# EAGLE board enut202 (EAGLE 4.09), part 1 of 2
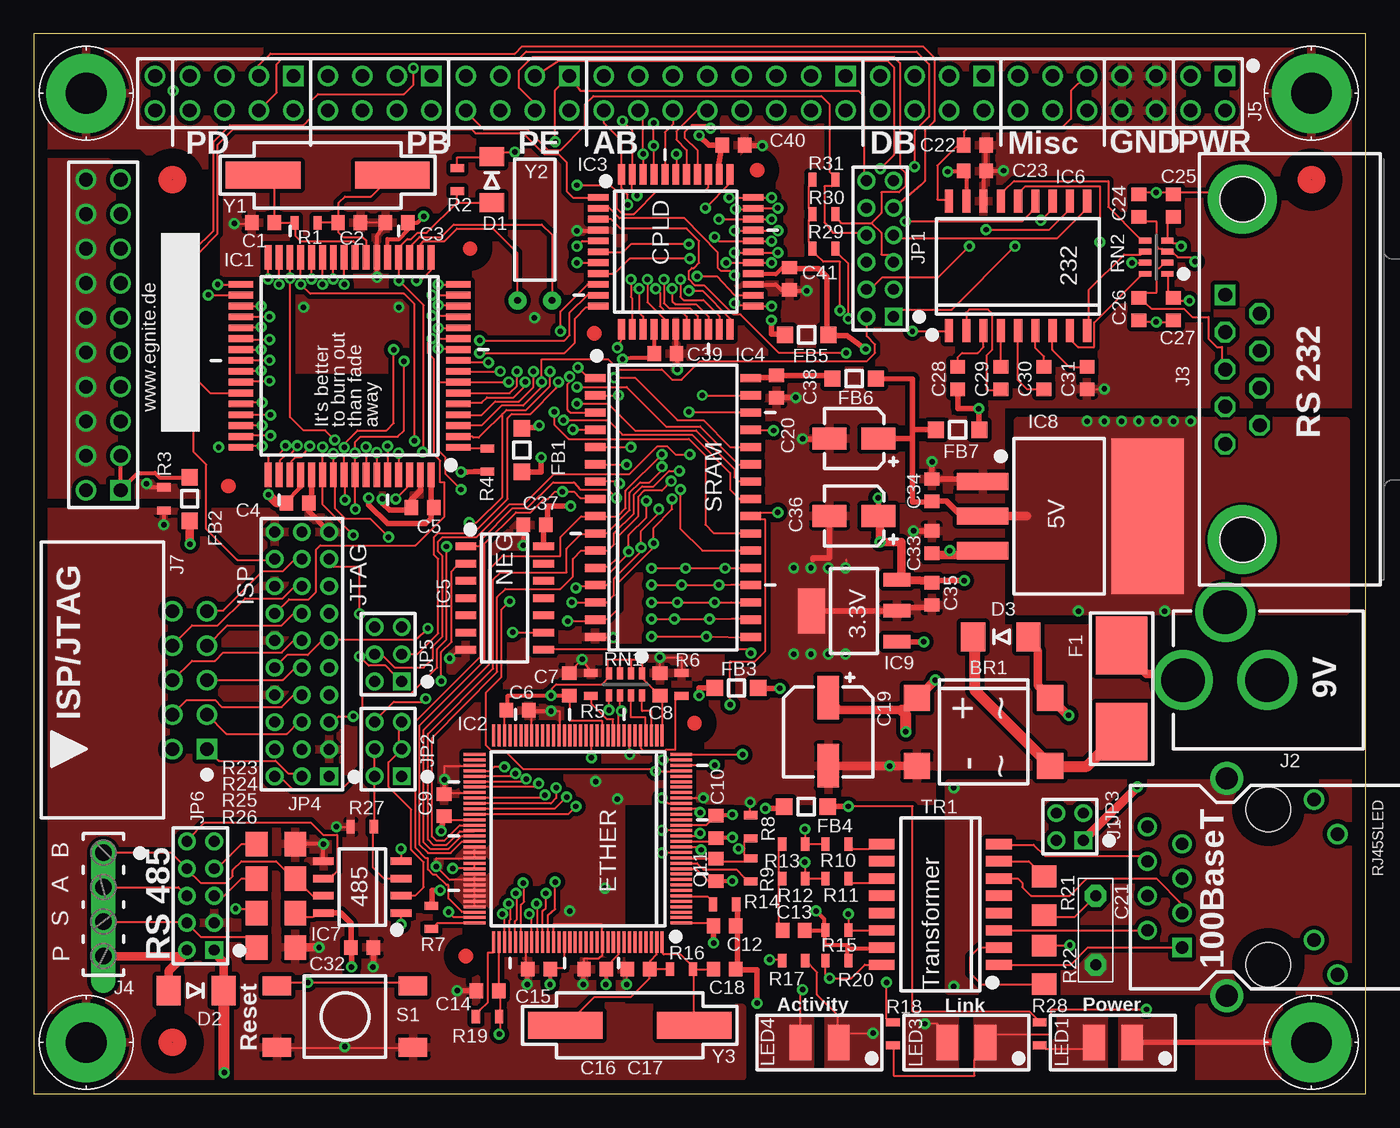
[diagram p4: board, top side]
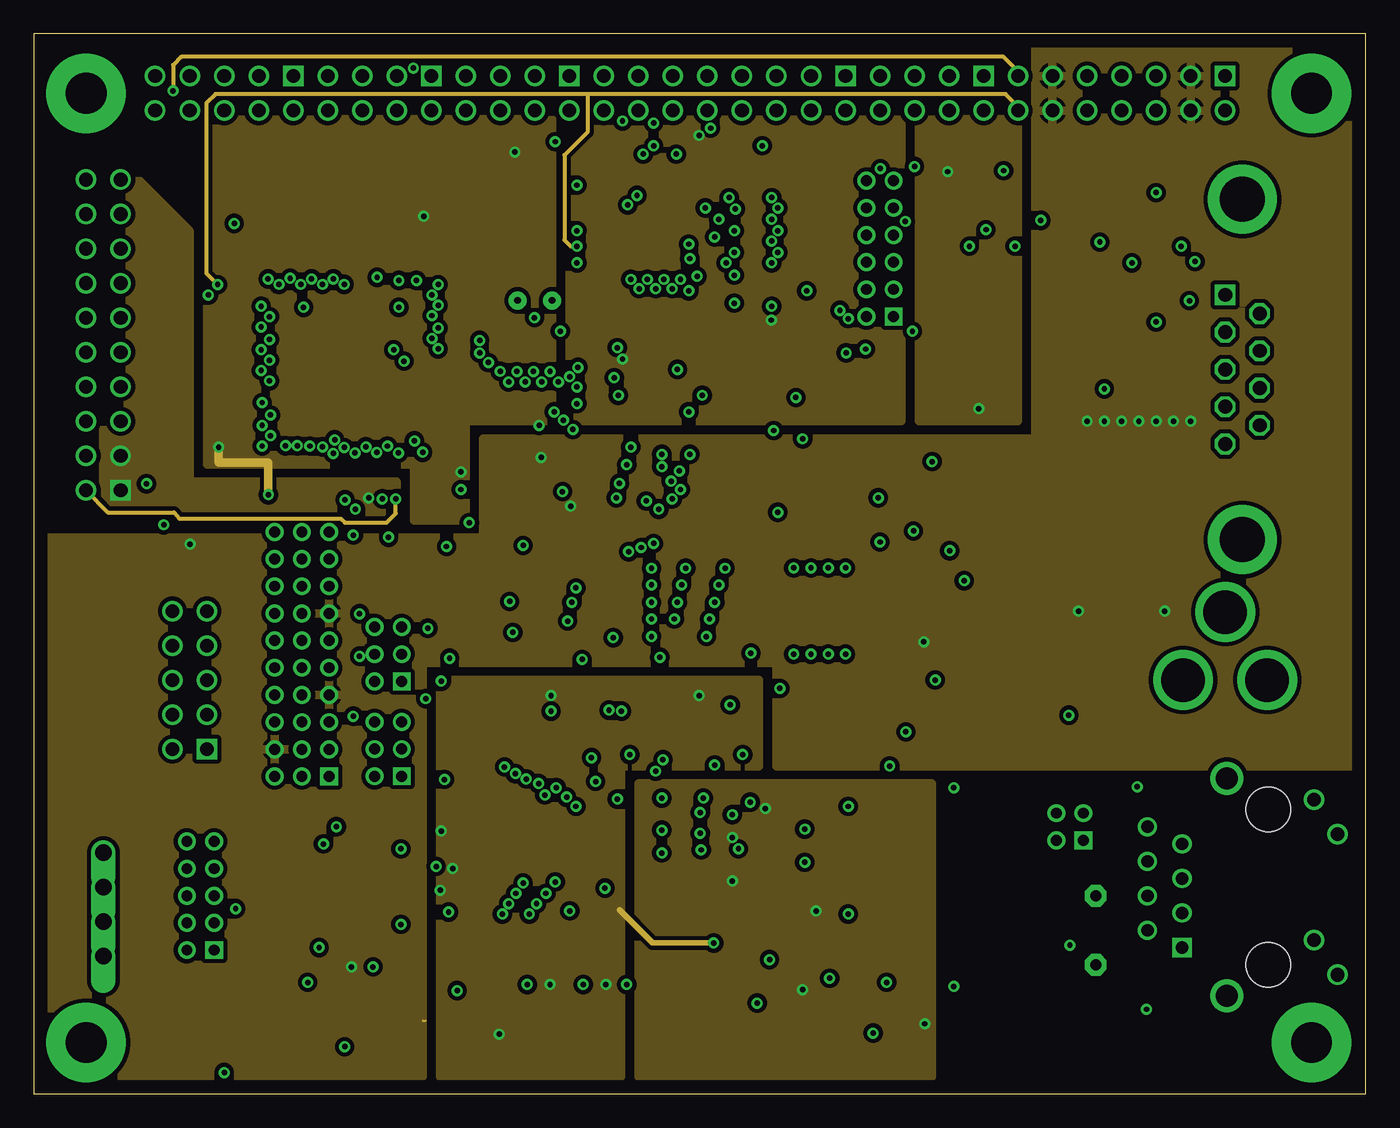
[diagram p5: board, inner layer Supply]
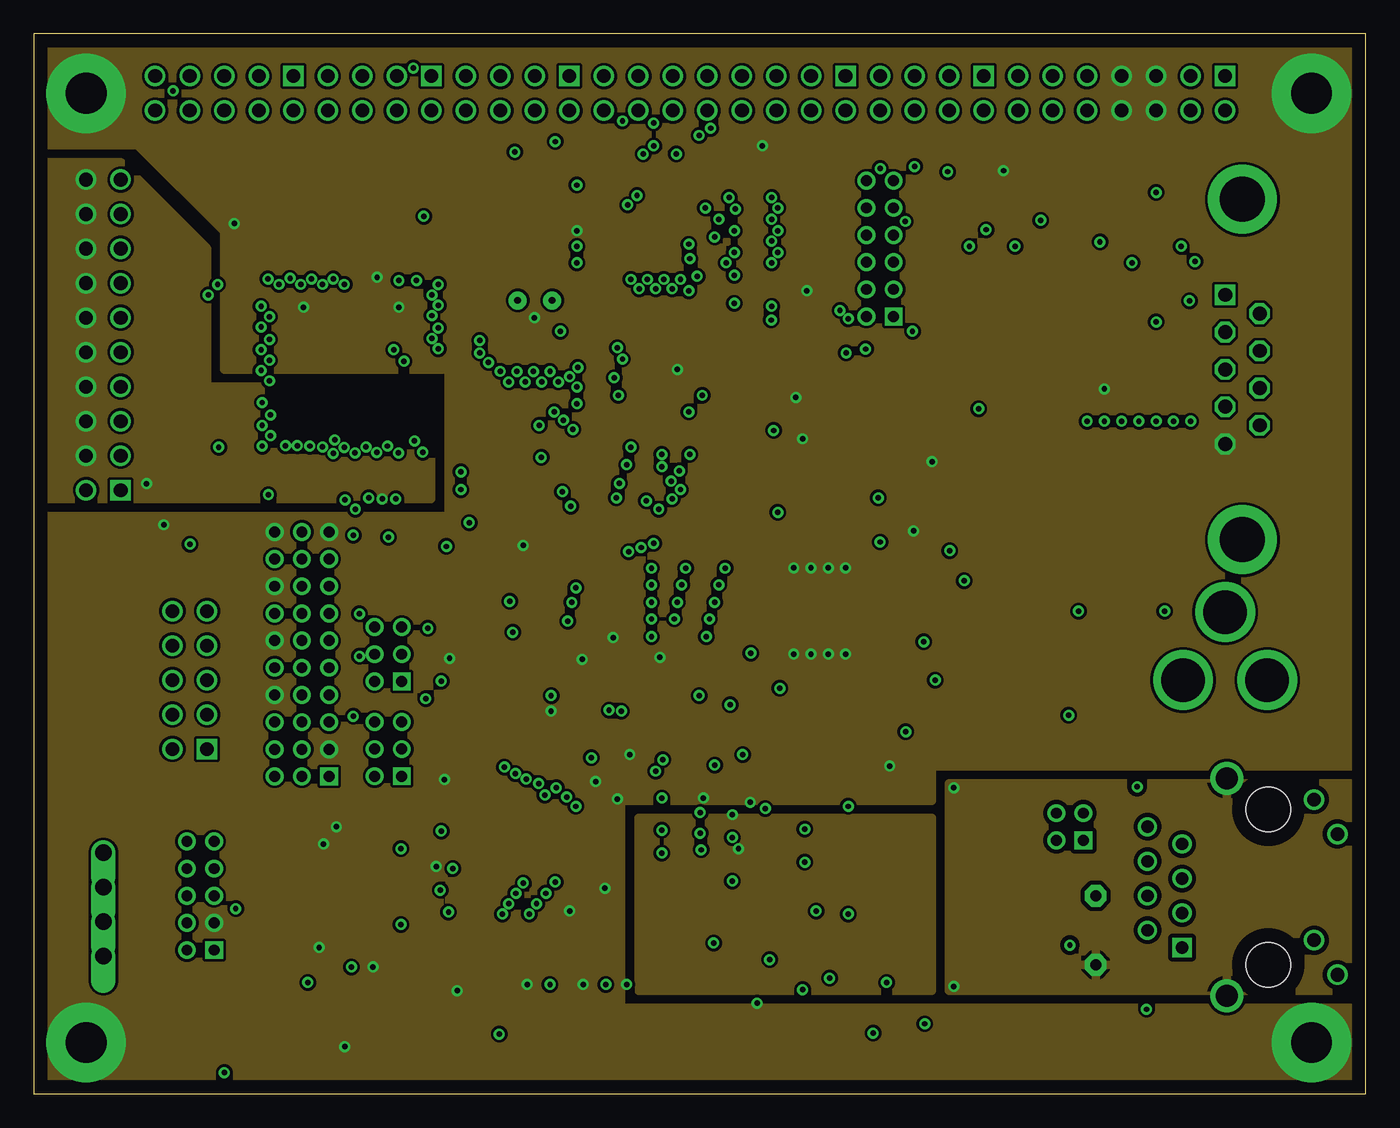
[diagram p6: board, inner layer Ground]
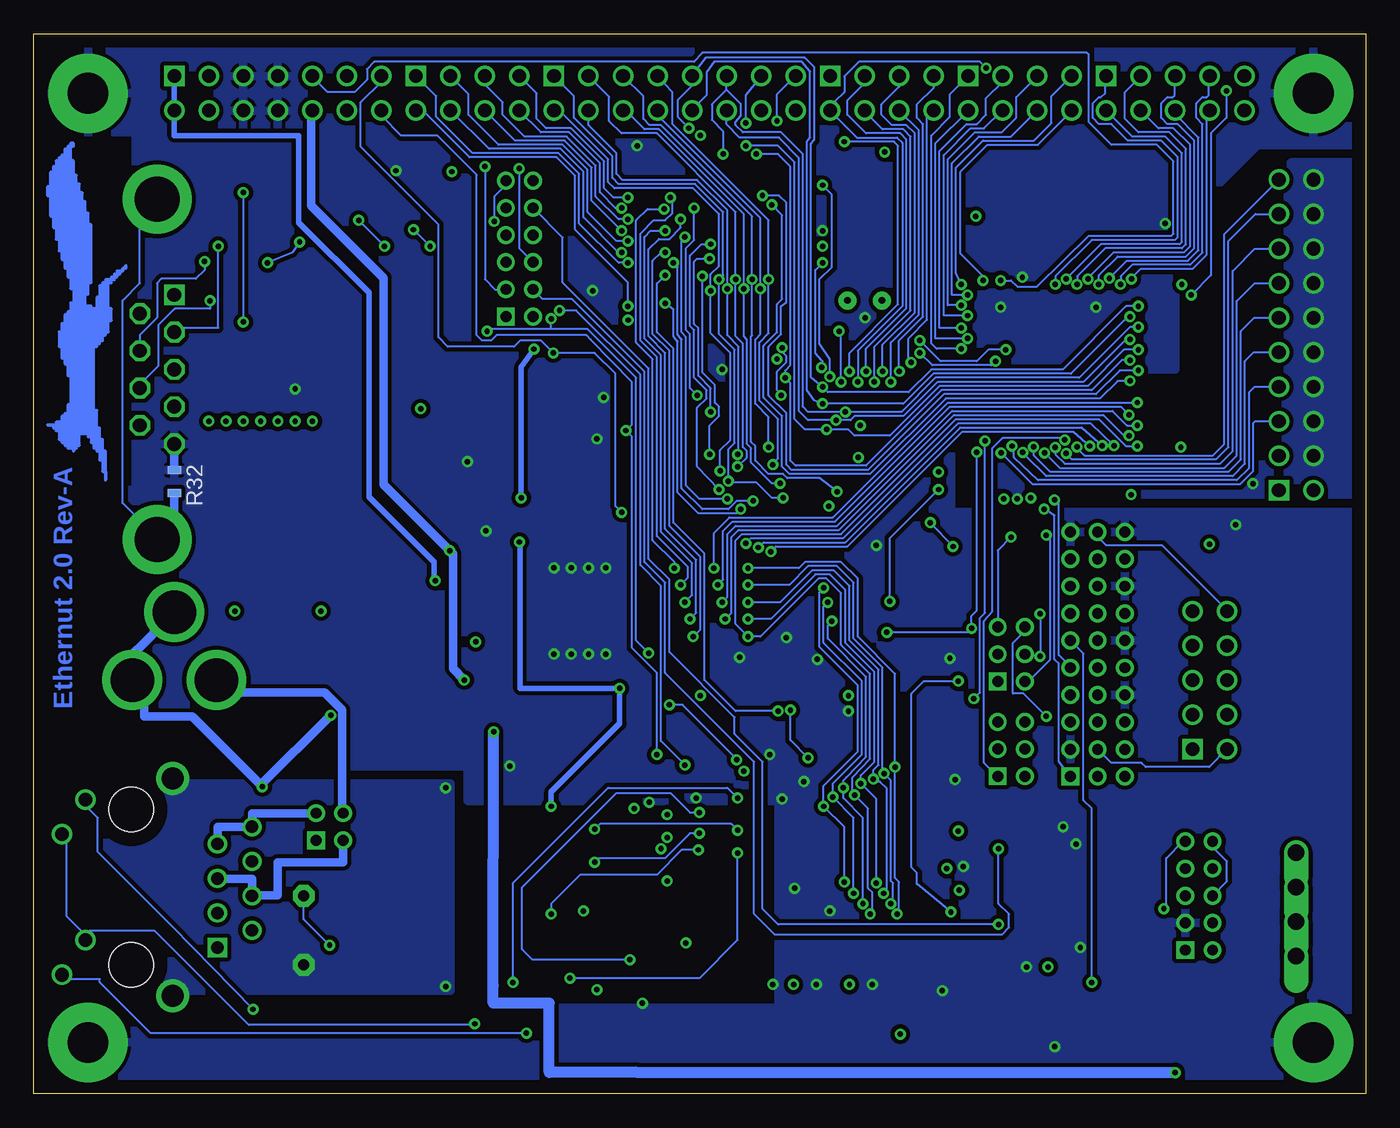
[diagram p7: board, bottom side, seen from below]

Size 97.99 x 78 mm. Coordinates in mm from the lower left corner, seen from the top.
Outline: 0,0 97.99,0 97.99,78 0,78 0,0
Copper layers used: Top, Supply, Ground, Bottom
Net classes: 1 Supply1A: width 0.61 mm

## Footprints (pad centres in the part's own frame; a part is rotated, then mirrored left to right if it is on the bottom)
DFS = smd 1.93 x 1.93: 1 -2.5,-4.9; 2 2.5,-4.9; 3 2.5,4.9; 4 -2.5,4.9
C0603 = smd 0.991 x 1.092: 1 -0.824,0; 2 0.824,0
ALUC6.3 = smd 3.2 x 1.6: + -2.5,0; - 2.5,0
ALUC4.0 = smd 2.5 x 1.6: + -1.8,0; - 1.8,0
C5.0 = drill 0.813 pad 1.6 octagon: 1 -2.54,0; 2 2.54,0
SOD-80C = smd 1.4 x 1.8: A 1.7,0; C -1.7,0
SMB = smd 1.778 x 2.159: A 2.032,0; C -2.032,0
OMNI-BLOK = smd 4.242 x 3.81: 1 -3.175,0; 2 3.175,0
BLM31 = smd 1.2 x 1.2: 1 -1.6,0; 2 1.6,0
MOUNT3 = drill 3 pad 5.842 round: B3,0 0,0
TQFP64 = smd 0.5 x 1.8: 1 -6,-8; 2 -5.2,-8; 3 -4.4,-8; 4 -3.6,-8; 5 -2.8,-8; 6 -2,-8; 7 -1.2,-8; 8 -0.4,-8; 9 0.4,-8; 10 1.2,-8; 11 2,-8; 12 2.8,-8; 13 3.6,-8; 14 4.4,-8; 15 5.2,-8; 16 6,-8; 33 6,8; 34 5.2,8; 35 4.4,8; 36 3.6,8; 37 2.8,8; 38 2,8; 39 1.2,8; 40 0.4,8; 41 -0.4,8; 42 -1.2,8; 43 -2,8; 44 -2.8,8; 45 -3.6,8; 46 -4.4,8; 47 -5.2,8; 48 -6,8 | smd 1.8 x 0.5: 17 8,-6; 18 8,-5.2; 19 8,-4.4; 20 8,-3.6; 21 8,-2.8; 22 8,-2; 23 8,-1.2; 24 8,-0.4; 25 8,0.4; 26 8,1.2; 27 8,2; 28 8,2.8; 29 8,3.6; 30 8,4.4; 31 8,5.2; 32 8,6; 49 -8,6; 50 -8,5.2; 51 -8,4.4; 52 -8,3.6; 53 -8,2.8; 54 -8,2; 55 -8,1.2; 56 -8,0.4; 57 -8,-0.4; 58 -8,-1.2; 59 -8,-2; 60 -8,-2.8; 61 -8,-3.6; 62 -8,-4.4; 63 -8,-5.2; 64 -8,-6
TQFP128 = smd 0.222 x 1.6: 1 -6.2,-7.6; 2 -5.8,-7.6; 3 -5.4,-7.6; 4 -5,-7.6; 5 -4.6,-7.6; 6 -4.2,-7.6; 7 -3.8,-7.6; 8 -3.4,-7.6; 9 -3,-7.6; 10 -2.6,-7.6; 11 -2.2,-7.6; 12 -1.8,-7.6; 13 -1.4,-7.6; 14 -1,-7.6; 15 -0.6,-7.6; 16 -0.2,-7.6; 17 0.2,-7.6; 18 0.6,-7.6; 19 1,-7.6; 20 1.4,-7.6; 21 1.8,-7.6; 22 2.2,-7.6; 23 2.6,-7.6; 24 3,-7.6; 25 3.4,-7.6; 26 3.8,-7.6; 27 4.2,-7.6; 28 4.6,-7.6; 29 5,-7.6; 30 5.4,-7.6; 31 5.8,-7.6; 32 6.2,-7.6; 65 6.2,7.6; 66 5.8,7.6; 67 5.4,7.6; 68 5,7.6; 69 4.6,7.6; 70 4.2,7.6; 71 3.8,7.6; 72 3.4,7.6; 73 3,7.6; 74 2.6,7.6; 75 2.2,7.6; 76 1.8,7.6; 77 1.4,7.6; 78 1,7.6; 79 0.6,7.6; 80 0.2,7.6; 81 -0.2,7.6; 82 -0.6,7.6; 83 -1,7.6; 84 -1.4,7.6; 85 -1.8,7.6; 86 -2.2,7.6; 87 -2.6,7.6; 88 -3,7.6; 89 -3.4,7.6; 90 -3.8,7.6; 91 -4.2,7.6; 92 -4.6,7.6; 93 -5,7.6; 94 -5.4,7.6; 95 -5.8,7.6; 96 -6.2,7.6 | smd 1.6 x 0.222: 33 7.6,-6.2; 34 7.6,-5.8; 35 7.6,-5.4; 36 7.6,-5; 37 7.6,-4.6; 38 7.6,-4.2; 39 7.6,-3.8; 40 7.6,-3.4; 41 7.6,-3; 42 7.6,-2.6; 43 7.6,-2.2; 44 7.6,-1.8; 45 7.6,-1.4; 46 7.6,-1; 47 7.6,-0.6; 48 7.6,-0.2; 49 7.6,0.2; 50 7.6,0.6; 51 7.6,1; 52 7.6,1.4; 53 7.6,1.8; 54 7.6,2.2; 55 7.6,2.6; 56 7.6,3; 57 7.6,3.4; 58 7.6,3.8; 59 7.6,4.2; 60 7.6,4.6; 61 7.6,5; 62 7.6,5.4; 63 7.6,5.8; 64 7.6,6.2; 97 -7.6,6.2; 98 -7.6,5.8; 99 -7.6,5.4; 100 -7.6,5; 101 -7.6,4.6; 102 -7.6,4.2; 103 -7.6,3.8; 104 -7.6,3.4; 105 -7.6,3; 106 -7.6,2.6; 107 -7.6,2.2; 108 -7.6,1.8; 109 -7.6,1.4; 110 -7.6,1; 111 -7.6,0.6; 112 -7.6,0.2; 113 -7.6,-0.2; 114 -7.6,-0.6; 115 -7.6,-1; 116 -7.6,-1.4; 117 -7.6,-1.8; 118 -7.6,-2.2; 119 -7.6,-2.6; 120 -7.6,-3; 121 -7.6,-3.4; 122 -7.6,-3.8; 123 -7.6,-4.2; 124 -7.6,-4.6; 125 -7.6,-5; 126 -7.6,-5.4; 127 -7.6,-5.8; 128 -7.6,-6.2
VQFP44 = smd 0.5 x 1.5: 1 -4,-5.7; 2 -3.2,-5.7; 3 -2.4,-5.7; 4 -1.6,-5.7; 5 -0.8,-5.7; 6 0,-5.7; 7 0.8,-5.7; 8 1.6,-5.7; 9 2.4,-5.7; 10 3.2,-5.7; 11 4,-5.7; 23 4,5.7; 24 3.2,5.7; 25 2.4,5.7; 26 1.6,5.7; 27 0.8,5.7; 28 0,5.7; 29 -0.8,5.7; 30 -1.6,5.7; 31 -2.4,5.7; 32 -3.2,5.7; 33 -4,5.7 | smd 1.5 x 0.5: 12 5.7,-4; 13 5.7,-3.2; 14 5.7,-2.4; 15 5.7,-1.6; 16 5.7,-0.8; 17 5.7,0; 18 5.7,0.8; 19 5.7,1.6; 20 5.7,2.4; 21 5.7,3.2; 22 5.7,4; 34 -5.7,4; 35 -5.7,3.2; 36 -5.7,2.4; 37 -5.7,1.6; 38 -5.7,0.8; 39 -5.7,0; 40 -5.7,-0.8; 41 -5.7,-1.6; 42 -5.7,-2.4; 43 -5.7,-3.2; 44 -5.7,-4
TSOP2-32 = smd 0.6 x 1.5: 1 -9.525,-5.715; 2 -8.255,-5.715; 3 -6.985,-5.715; 4 -5.715,-5.715; 5 -4.445,-5.715; 6 -3.175,-5.715; 7 -1.905,-5.715; 8 -0.635,-5.715; 9 0.635,-5.715; 10 1.905,-5.715; 11 3.175,-5.715; 12 4.445,-5.715; 13 5.715,-5.715; 14 6.985,-5.715; 15 8.255,-5.715; 16 9.525,-5.715; 17 9.525,5.715; 18 8.255,5.715; 19 6.985,5.715; 20 5.715,5.715; 21 4.445,5.715; 22 3.175,5.715; 23 1.905,5.715; 24 0.635,5.715; 25 -0.635,5.715; 26 -1.905,5.715; 27 -3.175,5.715; 28 -4.445,5.715; 29 -5.715,5.715; 30 -6.985,5.715; 31 -8.255,5.715; 32 -9.525,5.715
SO14 = smd 0.559 x 1.524: 1 -3.81,-2.857; 2 -2.54,-2.857; 3 -1.27,-2.857; 4 0,-2.857; 5 1.27,-2.857; 6 2.54,-2.857; 7 3.81,-2.857; 8 3.81,2.857; 9 2.54,2.857; 10 1.27,2.857; 11 0,2.857; 12 -1.27,2.857; 13 -2.54,2.857; 14 -3.81,2.857
SO18W = smd 0.6 x 1.7: 1 -5.08,-4.763; 2 -3.81,-4.763; 3 -2.54,-4.763; 4 -1.27,-4.763; 5 0,-4.763; 6 1.27,-4.763; 7 2.54,-4.763; 8 3.81,-4.763; 9 5.08,-4.763; 10 5.08,4.763; 11 3.81,4.763; 12 2.54,4.763; 13 1.27,4.763; 14 0,4.763; 15 -1.27,4.763; 16 -2.54,4.763; 17 -3.81,4.763; 18 -5.08,4.763
SOIC8 = smd 0.559 x 1.524: 1 -1.905,-2.857; 2 -0.635,-2.857; 3 0.635,-2.857; 4 1.905,-2.857; 5 1.905,2.857; 6 0.635,2.857; 7 -0.635,2.857; 8 -1.905,2.857
DDPAK-ST = smd 1.27 x 3.81: 1 -2.54,-6.413; 2 0,-6.413; 3 2.54,-6.413 | smd 11.43 x 5.334: 4 0,5.715
SOT-223 = smd 1 x 2: 1 -2.261,-3.15; 2 0.025,-3.15; 3 2.311,-3.15 | smd 3.3 x 2: 4 0,3.15
RJ45S = drill 0.9 square: 1 4.445,-6.35 | drill 0.9 round: 2 3.175,-8.89; 3 1.905,-6.35; 4 0.635,-8.89; 5 -0.635,-6.35; 6 -1.905,-8.89; 7 -3.175,-6.35; 8 -4.445,-8.89 | drill 1 round: D1+ 6.452,5.08; D1- 3.912,3.378; D2+ -6.452,3.378; D2- -3.912,5.08 | drill 1.63 round: S1 8.001,-3.048; S2 -8.001,-3.048 | hole 3.3: 5.715,0; -5.715,0
DC2.1 = drill 3.2 pad 4.4 round: 1 -6.91,0; 2 -0.71,0; 3 -3.81,5
SUBD9F = drill 1.016 pad 1.524 square: 1 -5.486,-5.08 | drill 1.016 pad 1.524 octagon: 2 -2.743,-5.08; 3 0,-5.08; 4 2.743,-5.08; 5 5.486,-5.08; 6 -4.115,-2.54; 7 -1.372,-2.54; 8 1.372,-2.54; 9 4.115,-2.54 | drill 3.302 pad 5.08 round: G1 -12.522,-3.81; G2 12.522,-3.81
MINISK = drill 1.2 offset: 1 -3.81,0; 2 -1.27,0; 3 1.27,0; 4 3.81,0
NUTEXP = drill 1 square: 1 39.37,1.27; 15 21.59,1.27; 23 11.43,1.27; 39 -8.89,1.27; 47 -19.05,1.27; 55 -29.21,1.27 | drill 1 round: 2 39.37,-1.27; 3 36.83,1.27; 4 36.83,-1.27; 5 34.29,1.27; 6 34.29,-1.27; 7 31.75,1.27; 8 31.75,-1.27; 9 29.21,1.27; 10 29.21,-1.27; 11 26.67,1.27; 12 26.67,-1.27; 13 24.13,1.27; 14 24.13,-1.27; 16 21.59,-1.27; 17 19.05,1.27; 18 19.05,-1.27; 19 16.51,1.27; 20 16.51,-1.27; 21 13.97,1.27; 22 13.97,-1.27; 24 11.43,-1.27; 25 8.89,1.27; 26 8.89,-1.27; 27 6.35,1.27; 28 6.35,-1.27; 29 3.81,1.27; 30 3.81,-1.27; 31 1.27,1.27; 32 1.27,-1.27; 33 -1.27,1.27; 34 -1.27,-1.27; 35 -3.81,1.27; 36 -3.81,-1.27; 37 -6.35,1.27; 38 -6.35,-1.27; 40 -8.89,-1.27; 41 -11.43,1.27; 42 -11.43,-1.27; 43 -13.97,1.27; 44 -13.97,-1.27; 45 -16.51,1.27; 46 -16.51,-1.27; 48 -19.05,-1.27; 49 -21.59,1.27; 50 -21.59,-1.27; 51 -24.13,1.27; 52 -24.13,-1.27; 53 -26.67,1.27; 54 -26.67,-1.27; 56 -29.21,-1.27; 57 -31.75,1.27; 58 -31.75,-1.27; 59 -34.29,1.27; 60 -34.29,-1.27; 61 -36.83,1.27; 62 -36.83,-1.27; 63 -39.37,1.27; 64 -39.37,-1.27
SLLP2X10 = drill 1 square: 1 -11.43,-1.27 | drill 1 round: 2 -11.43,1.27; 3 -8.89,-1.27; 4 -8.89,1.27; 5 -6.35,-1.27; 6 -6.35,1.27; 7 -3.81,-1.27; 8 -3.81,1.27; 9 -1.27,-1.27; 10 -1.27,1.27; 11 1.27,-1.27; 12 1.27,1.27; 13 3.81,-1.27; 14 3.81,1.27; 15 6.35,-1.27; 16 6.35,1.27; 17 8.89,-1.27; 18 8.89,1.27; 19 11.43,-1.27; 20 11.43,1.27
ML10A = drill 1 pad 1.422 square: 1 -5.08,-6.35 | drill 1 pad 1.422 round: 2 -5.08,-3.81; 3 -2.54,-6.35; 4 -2.54,-3.81; 5 0,-6.35; 6 0,-3.81; 7 2.54,-6.35; 8 2.54,-3.81; 9 5.08,-6.35; 10 5.08,-3.81
SLY2X6 = drill 0.8 square: 1 -5,-1 | drill 0.8 round: 2 -5,1; 3 -3,-1; 4 -3,1; 5 -1,-1; 6 -1,1; 7 1,-1; 8 1,1; 9 3,-1; 10 3,1; 11 5,-1; 12 5,1
SLY2X3 = drill 0.8 square: 1 -2,-1 | drill 0.8 round: 2 -2,1; 3 0,-1; 4 0,1; 5 2,-1; 6 2,1
SLY2X2 = drill 0.8 square: 1 -1,-1 | drill 0.8 round: 2 -1,1; 3 1,-1; 4 1,1
SLY3X10 = drill 0.8 square: 1A -9,-2 | drill 0.8 round: 1B -9,0; 1C -9,2; 2A -7,-2; 2B -7,0; 2C -7,2; 3A -5,-2; 3B -5,0; 3C -5,2; 4A -3,-2; 4B -3,0; 4C -3,2; 5A -1,-2; 5B -1,0; 5C -1,2; 6A 1,-2; 6B 1,0; 6C 1,2; 7A 3,-2; 7B 3,0; 7C 3,2; 8A 5,-2; 8B 5,0; 8C 5,2; 9A 7,-2; 9B 7,0; 9C 7,2; 10A 9,-2; 10B 9,0; 10C 9,2
SLY2X5 = drill 0.8 square: 1 -4,-1 | drill 0.8 round: 2 -4,1; 3 -2,-1; 4 -2,1; 5 0,-1; 6 0,1; 7 2,-1; 8 2,1; 9 4,-1; 10 4,1
P-LCC-2 = smd 1.6 x 2.6: A 1.4,0; C -1.4,0
R0603 = smd 0.6 x 1: 1 -0.85,0; 2 0.85,0
R1206 = smd 1.6 x 1.803: 1 -1.422,0; 2 1.422,0
CAY16 = smd 0.432 x 0.889: 1 -1.219,-0.813; 2 -0.406,-0.813; 3 0.406,-0.813; 4 1.219,-0.813; 5 1.219,0.813; 6 0.406,0.813; 7 -0.406,0.813; 8 -1.219,0.813
LSH = smd 2.1 x 1.4: 1 -5,-2.25; 2 5,-2.25; 3 -5,2.25; 4 5,2.25
SOIC16-12TR = smd 0.762 x 1.905: 1 -4.445,-4.318; 2 -3.175,-4.318; 3 -1.905,-4.318; 4 -0.635,-4.318; 5 0.635,-4.318; 6 1.905,-4.318; 7 3.175,-4.318; 8 4.445,-4.318; 9 4.445,4.318; 10 3.175,4.318; 11 1.905,4.318; 12 0.635,4.318; 13 -0.635,4.318; 14 -1.905,4.318; 15 -3.175,4.318; 16 -4.445,4.318
HC49SM = smd 5.5 x 2: P$1 4.75,0; P$2 -4.75,0
TC38 = drill 0.5 pad 1.321 round: 1 -1.27,-5.08; 2 1.27,-5.08

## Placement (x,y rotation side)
BR1  DF005S  [DFS]  69.88,26.64 270 top
C1  22p  [C0603]  16.86,64.11 180 top
C2  22p  [C0603]  23.21,64.11 0 top
C3  100n  [C0603]  26.7,64.11 180 top
C4  100n  [C0603]  19.4,43.47 0 top
C5  100n  [C0603]  28.61,43.15 180 top
C6  100n  [C0603]  35.59,28.23 0 top
C7  100n  [C0603]  39.4,30.13 90 top
C8  100n  [C0603]  46.07,30.13 90 top
C9  100n  [C0603]  30.19,21.24 90 top
C10  100n  [C0603]  50.2,19.65 90 top
C11  100n  [C0603]  50.2,16.48 90 top
C12  100n  [C0603]  50.83,12.35 0 top
C13  10n  [C0603]  55.91,12.04 180 top
C14  100n  [C0603]  33.37,7.59 180 top
C15  100n  [C0603]  37.18,9.18 180 top
C16  100n  [C0603]  41.3,9.18 180 top
C17  22p  [C0603]  44.48,9.18 180 top
C18  22p  [C0603]  50.83,9.18 0 top
C19  100u 25V  [ALUC6.3]  58.45,26.64 270 top
C20  10u 16V  [ALUC4.0]  60.36,48.23 180 top
C21  1n 2kV  [C5.0]  78.14,12.04 270 top
C22  47n  [C0603]  69.25,69.82 0 top
C23  100n  [C0603]  69.25,67.91 0 top
C24  220p  [C0603]  81.31,65.38 90 top
C25  220p  [C0603]  83.85,65.38 90 top
C26  220p  [C0603]  81.31,57.75 270 top
C27  220p  [C0603]  83.85,57.75 270 top
C28  100n  [C0603]  67.97,52.67 90 top
C29  100n  [C0603]  71.15,52.67 90 top
C30  100n  [C0603]  74.33,52.67 90 top
C31  100n  [C0603]  77.5,52.67 90 top
C32  100n  [C0603]  24.16,10.77 0 top
C33  100n  [C0603]  66.07,40.61 90 top
C34  100n  [C0603]  66.07,44.42 90 top
C35  100n  [C0603]  66.07,36.8 270 top
C36  10u 16V  [ALUC4.0]  60.36,42.52 180 top
C37  100n  [C0603]  36.84,41.88 180 top
C38  100n  [C0603]  54.64,52.04 270 top
C39  100n  [C0603]  46.46,54.47 0 top
C40  100n  [C0603]  51.46,69.82 0 top
C41  100n  [C0603]  55.59,59.98 270 top
D1  LL4148  [SOD-80C]  33.69,67.28 270 top
D2  S1G  [SMB]  11.94,7.59 180 top
D3  SM6T15CA  [SMB]  71.15,33.62 0 top
F1  1A  [OMNI-BLOK]  80.04,29.81 270 top
FB1  BLM31A601  [BLM31]  35.89,47.38 90 top
FB2  BLM31A601  [BLM31]  11.46,43.78 90 top
FB3  BLM31A601  [BLM31]  51.7,29.87 180 top
FB4  BLM31A601  [BLM31]  56.82,21.13 0 top
FB5  BLM31A601  [BLM31]  56.86,55.85 0 top
FB6  BLM31A601  [BLM31]  60.36,52.64 0 top
FB7  BLM31A601  [BLM31]  67.97,48.87 180 top
H1  [MOUNT3]  3.84,73.63 0 top
H2  [MOUNT3]  3.84,3.78 0 top
H3  [MOUNT3]  94.01,73.63 0 top
H4  [MOUNT3]  94.01,3.78 0 top
IC1  ATMEGA128-AC  [TQFP64]  23.23,53.57 90 top
IC2  LAN91C111-NE  [TQFP128]  40.03,18.77 90 top
IC3  XC9536XLVQ44  [VQFP44]  47.23,61.97 270 top
IC4  K6T4008C1C-VB70  [TSOP2-32]  47.02,43.15 270 top
IC5  74HC04D  [SO14]  34.64,36.48 270 top
IC6  MAX3222ECWN  [SO18W]  72.42,60.93 0 top
IC7  SP483ECN  [SOIC8]  24.16,15.21 90 top
IC8  LM1086IS  [DDPAK-ST]  76.23,42.52 270 top
IC9  LM3940IMP  [SOT-223]  60.36,35.53 90 top
J1  RJ45SLED  [RJ45S]  90.84,15.21 270 top
J2  [DC2.1]  91.47,30.45 0 top
J3  [SUBD9F]  92.74,53.31 270 top
J4  [MINISK]  5.11,13.94 270 top
J5  [NUTEXP]  48.29,73.63 0 top
J6  [SLLP2X10]  5.11,55.85 90 top
J7  [ML10A]  6.38,30.45 90 top
JP1  [SLY2X6]  62.26,62.2 90 top
JP2  [SLY2X3]  26.07,25.37 90 top
JP3  [SLY2X2]  76.23,19.65 90 top
JP4  [SLY3X10]  19.71,32.35 90 top
JP5  [SLY2X3]  26.07,32.35 90 top
JP6  JP2X5-1E  [SLY2X5]  12.25,14.58 90 top
LED1  LTST-T670KRKT  [P-LCC-2]  79.41,3.78 180 top
LED3  LTST-T670KGKT  [P-LCC-2]  68.61,3.78 180 top
LED4  LTST-T670KSKT  [P-LCC-2]  57.81,3.78 180 top
R1  1M  [R0603]  20.03,64.11 0 top
R2  10k  [R0603]  31.14,67.28 90 top
R3  0  [R0603]  9.55,43.78 90 top
R4  4k7  [R0603]  33.37,46.64 270 top
R5  10k  [R0603]  40.99,30.13 270 top
R6  10k  [R0603]  47.66,30.13 270 top
R7  10k  [R0603]  29.24,12.99 270 top
R8  0  [R0603]  52.73,19.65 270 top
R9  11k  [R0603]  52.73,16.48 270 top
R10  24.9  [R0603]  59.09,18.38 0 top
R11  24.9  [R0603]  59.09,15.85 0 top
R12  24.9  [R0603]  55.91,15.85 180 top
R13  24.9  [R0603]  55.91,18.38 180 top
R14  10k  [R0603]  50.83,13.94 180 top
R15  49.9  [R0603]  59.09,12.04 180 top
R16  1M  [R0603]  47.66,9.18 180 top
R17  660  [R0603]  55.91,9.81 0 top
R18  660  [R0603]  63.21,4.42 270 top
R19  10k  [R0603]  33.37,5.68 180 top
R20  49.9  [R0603]  59.09,9.81 0 top
R21  75  [R1206]  74.33,14.58 90 top
R22  75  [R1206]  74.33,9.5 270 top
R23  560  [R1206]  17.81,18.38 180 top
R24  120  [R1206]  17.81,15.85 180 top
R25  560  [R1206]  17.81,13.31 0 top
R26  100  [R1206]  17.81,10.77 0 top
R27  10k  [R0603]  24.16,19.65 0 top
R28  660  [R0603]  74.01,4.42 90 top
R29  1k  [R0603]  58.13,62.2 180 top
R30  1k  [R0603]  58.13,64.74 180 top
R31  1k  [R0603]  58.13,67.28 180 top
R32  0  [R0603]  87.66,45.05 270 bottom
RN1  10k  [CAY16]  43.53,30.13 180 top
RN2  22  [CAY16]  82.58,61.56 90 top
S1  LSH  [LSH]  22.89,5.68 180 top
TR1  TG110-S050N2  [SOIC16-12TR]  66.7,13.94 90 top
U$4  [LOGO]  91.23,45.16 90 bottom
U$9  [MARK1]  14.32,44.74 0 top
U$10  [MARK1]  32.1,62.2 0 top
U$11  [MARK1]  31.78,10.13 0 top
U$12  [MARK1]  48.61,27.27 0 top
U$13  [MARK1]  41.23,55.96 0 top
U$14  [MARK1]  53.23,67.97 0 top
U$15  [MARK2]  10.19,67.28 0 top
U$16  [MARK2]  94.01,67.28 0 top
U$17  [MARK2]  10.19,3.78 0 top
Y1  14.7456 MHz  [HC49SM]  21.62,67.6 180 top
Y2  32k768  [TC38]  36.86,63.47 0 top
Y3  25 MHz  [HC49SM]  43.84,5.05 0 top

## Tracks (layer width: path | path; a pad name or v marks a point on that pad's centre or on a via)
A0  (via drill 0.4)
  Top 0.152: 50.47,56.31 IC3.21 50.43,57.24 49.26,58.41 47.81,58.41 47.58,58.64 v47.58,59.94 | v46.89,45.08 46.21,44.39 44.91,44.39 44.45,43.94 44.45,42.49 43.01,41.04 43.01,39.52 42.25,38.76 41.41,38.76 41.36,38.7 IC4.12 | 32.87,40.29 IC5.1 | v42.85,43.86 42.25,44.47 40.19,44.47 39.73,45 38.21,45 36.3,43.1 35.23,43.1 32.87,40.74 32.87,40.29 | 32.41,13.38 IC2.94 31.65,13.38 31.5,13.38 30.51,14.37 30.51,15.36 30.36,15.36 29.6,16.12 29.37,16.12 28.99,16.5 28.99,17.34 28.83,17.34 28.07,18.11 28.07,27.4 32.87,32.2 32.87,40.29
  Bottom 0.152: J5.23 58.25,73.43 58.25,71.83 55.43,69.01 55.43,67.41 54.97,66.95 49.33,66.95 47.27,64.89 47.27,60.24 v47.58,59.94 47.58,55.9 46.44,54.76 46.44,47.9 46.89,47.44 v46.89,45.08 46.82,45 44.84,45 43.69,43.86 v42.85,43.86
A0\  (via drill 0.4)
  Top 0.152: IC2.95 31.65,13 30.89,13 v30.51,13.38 | IC5.2 31.04,38.76 30.74,38.45 30.74,33.27 29.98,32.51 v29.98,30.37
  Bottom 0.152: v29.98,30.37 32.49,30.37 33.41,29.46 33.41,16.66 33.02,16.28 33.02,15.44 v30.51,13.38
A1  (via drill 0.4)
  Top 0.152: IC2.78 | 41.33,39.98 41.33,39.97 | IC4.11 41.33,39.98 | IC3.22 51.23,57.05 49.18,59.1 v48.19,59.1 | v47.5,45.84 46.74,45.84 45.6,44.7 44.76,44.7 44.15,44.09 44.15,42.72 42.7,41.27 42.7,40.43 42.25,39.98 41.33,39.98 | IC4.11 | IC4.11 40.26,39.98 39.65,39.37 39.65,38.07 38.74,37.16 34.7,37.16 34.09,36.55 34.09,31.06 33.94,30.91 29.29,26.18 29.29,18.94 29.6,18.64 30.21,18.64 31.34,19.77 IC2.78 | 41.33,39.98 | 41.33,39.98 | IC2.78 32.43,19.78
  Bottom 0.152: 59.77,72.36 J5.24 59.31,72.36 55.73,68.78 55.73,67.1 55.27,66.64 49.48,66.64 47.58,64.74 47.58,60.93 48.19,60.32 v48.19,59.1 48.19,55.98 46.74,54.53 46.74,48.13 47.5,47.37 v47.5,45.84
A2  (via drill 0.4)
  Top 0.152: 48.87,56.27 IC3.19 48.83,57.24 48.27,57.81 46.74,57.81 46.36,58.19 v46.36,59.94 | v46.21,46.15 46.21,45.92 45.29,45 44.61,45 43.84,44.24 43.84,42.95 42.17,41.27 41.41,41.27 41.38,41.24 IC4.10 41.25,41.19 40.26,41.19 39.2,40.13 39.2,38.38 34.32,38.38 33.79,37.84 33.79,31.29 28.99,26.49 28.99,18.71 29.37,18.33 30.36,18.33 31.35,19.32 32.39,19.32 IC2.79
  Bottom 0.152: J5.25 55.66,73.38 55.66,71.6 54.74,70.68 52.15,70.68 46.36,64.89 v46.36,59.94 46.36,55.75 45.83,55.21 45.83,47.59 45.52,47.29 45.52,46.83 v46.21,46.15
A3  (via drill 0.4)
  Top 0.152: IC2.80 | IC2.80 | IC3.20 49.63,57.2 48.72,58.11 47.2,58.11 46.97,58.34 v46.97,59.25 | v46.21,47.06 43.54,44.39 43.54,43.1 42.93,42.49 41.33,42.49 | 41.33,42.49 IC4.9 | 41.33,42.49 40.26,42.49 38.74,40.97 38.74,39.59 34.47,39.59 33.48,38.6 33.48,31.59 28.68,26.79 28.68,18.49 29.14,18.03 30.51,18.03 31.45,18.97 IC2.80
  Bottom 0.152: v46.21,47.06 46.13,47.14 46.13,54.99 46.97,55.82 v46.97,59.25 46.97,65.05 49.18,67.25 54.66,67.25 55.12,67.71 55.12,69.24 57.18,71.29 J5.26
A4  (via drill 0.4)
  Top 0.152: IC2.81 | IC4.8 41.33,43.77 | IC4.8 | IC2.81 | IC3.16 46.44,56.28 46.36,56.36 | 46.36,56.36 46.44,56.43 | 46.36,56.36 46.36,57.04 45.14,58.26 v45.14,59.94 | 41.39,43.86 IC4.8 | 41.39,43.86 41.41,43.86 | 41.39,43.86 40.19,43.86 39.73,44.32 v38.89,44.32 38.36,44.32 37.83,43.78 37.52,43.78 36.53,42.79 35.46,42.79 33.18,40.51 33.18,31.9 28.38,27.1 28.38,18.33 28.99,17.72 30.66,17.72 31.51,18.57 IC2.81
  Bottom 0.152: J5.27 53.14,73.4 53.14,71.75 52.68,71.29 51.85,71.29 45.14,64.59 v45.14,59.94 45.14,55.82 45.22,55.75 45.22,47.98 44.91,47.67 44.91,46.6 43.92,45.61 42.85,45.61 42.55,45.31 40.19,45.31 v38.89,44.32
A5  (via drill 0.4)
  Top 0.152: IC3.18 | IC3.18 48.04,56.28 | IC3.18 48.03,57.2 47.73,57.5 46.51,57.5 46.05,57.96 46.05,58.95 v45.75,59.25 | IC4.7 41.33,45.08 42.93,45.08 v43.08,44.93 | IC4.7
  Bottom 0.152: v43.08,44.93 43.69,44.93 45.22,46.45 45.22,47.52 45.52,47.82 45.52,55.52 45.75,55.75 v45.75,59.25 45.75,64.74 52,70.99 53.06,70.99 54.44,72.36 J5.28 54.66,72.36
A6  (via drill 0.4)
  Top 0.152: IC3.13 44,56.27 44,58.57 43.92,58.64 v43.92,59.94 | IC4.6 41.3,46.35 41.33,46.38 41.41,46.3 v43.62,46.3
  Bottom 0.152: J5.29 51.01,73.73 51.01,71.37 43.92,64.28 v43.92,59.94 43.92,55.98 44.61,55.29 44.61,51.02 43.23,49.65 43.23,46.76 43.62,46.38 v43.62,46.3
A7  (via drill 0.4)
  Top 0.152: IC3.14 44.83,57.2 44.53,57.5 v44.53,59.25 | 41.33,47.59 | IC4.5 41.33,47.59 | 41.33,47.59 v43.92,47.59
  Bottom 0.152: J5.30 52.15,72.36 52.15,72.05 44.53,64.44 v44.53,59.25 44.53,55.9 44.91,55.52 44.91,50.8 43.92,49.8 v43.92,47.59
A8  (via drill 0.4)
  Top 0.152: IC1.35 15.25,57.96 v16.72,57.96 | v39.96,52.02 43.62,52.02 46.51,49.12 49.03,49.12 51.85,46.3 52.71,46.3 IC4.27 | IC3.37 48.83,69.43 47.88,70.38 47.88,70.76 48.42,71.29 49.41,71.29 v49.79,71.06
  Bottom 0.152: v16.72,57.96 17.63,57.96 22.28,53.31 31.96,53.31 33.63,51.63 39.58,51.63 v39.96,52.02 40.8,52.7 40.8,69.92 40.57,70.23 40.57,75.56 41.25,76.25 48.57,76.25 49.56,74.95 J5.31 49.56,74.19 50.63,73.12 50.63,71.9 v49.79,71.06
A9  (via drill 0.4)
  Top 0.152: IC1.36 15.26,57.2 v17.33,57.2 | v39.96,50.8 42.25,50.8 44.23,48.81 48.72,48.81 51.54,45.99 51.54,45.38 51.85,45.08 52.71,45.08 IC4.26 | J5.32 48.8,72.36 47.27,70.84 47.27,70.23 48.04,69.46 48.03,69.46 IC3.38
  Bottom 0.152: J5.32 49.56,72.44 48.49,73.5 48.49,75.18 47.96,75.94 41.48,75.94 40.87,75.26 40.87,70.38 41.1,70.07 41.1,51.79 40.57,51.02 v39.96,50.8 34.02,50.8 31.8,53 21.67,53 17.48,57.2 v17.33,57.2
A10  (via drill 0.4)
  Top 0.152: IC1.37 15.29,56.43 v16.72,56.43 | IC3.39 47.27,66.95 v47.27,69.16 | v38.28,50.19 38.28,49.27 39.35,48.2 48.19,48.2 49.41,46.98 49.41,41.88 50.02,41.27 52.71,41.27 IC4.23
  Bottom 0.152: 47,74.9 J5.33 47.05,74.88 47.05,73.88 | 47.05,73.88 48.11,72.82 48.11,71.67 47.27,70.84 v47.27,69.16 | 47.05,73.88 45.98,72.82 45.98,71.98 46.36,71.52 46.36,71.29 45.83,70.76 43.01,70.76 41.41,69.16 41.41,50.57 41.03,50.19 v38.28,50.19 34.17,50.19 31.65,52.7 21.06,52.7 17.33,56.43 v16.72,56.43
A11  (via drill 0.4)
  Top 0.152: IC3.40 46.43,70.75 47.05,71.37 47.05,72.33 J5.34 | IC1.38 15.29,55.52 v17.33,55.52 | 52.68,43.78 | 52.68,43.78 IC4.25 | 52.68,43.78 | v38.97,49.58 42.25,49.58 43.31,48.51 48.42,48.51 51.24,45.69 51.24,44.47 51.92,43.78 52.68,43.78
  Bottom 0.152: 47.05,71.67 47.05,71.37 46.05,70.38 43.16,70.38 41.71,68.86 41.71,50.26 41.03,49.58 v38.97,49.58 37.9,49.58 37.6,49.88 34.02,49.88 31.5,52.4 20.76,52.4 17.63,55.52 v17.33,55.52 | 47.05,71.67 47.05,72.36 | 47.05,71.67 J5.34
A12  (via drill 0.4)
  Top 0.152: IC1.39 15.25,54.76 v16.72,54.76 | IC4.4 41.28,48.89 v39.65,48.89 | v45.6,71.45 v45.6,69.77 45.6,67.56 IC3.41
  Bottom 0.152: v45.6,69.77 43.23,69.77 42.02,68.55 42.02,49.65 41.25,48.89 v39.65,48.89 38.05,48.89 37.6,48.43 35.01,48.43 31.35,52.09 20.45,52.09 17.79,54.76 v16.72,54.76 | J5.35 44.45,74.88 45.6,73.5 v45.6,71.45
A13  (via drill 0.4)
  Top 0.152: IC1.40 15.26,54 v17.33,54 | J5.36 44.53,72.36 44.84,72.05 v44.84,69.16 44.84,67.56 IC3.42 | IC4.28 | IC4.28 51.24,47.59 49.26,49.58 47.35,49.58 44.23,52.7 v42.7,52.7
  Bottom 0.152: v44.84,69.16 43.23,69.16 42.32,68.25 42.32,53.62 42.7,53.23 v42.7,52.7 42.32,52.32 42.32,46.6 41.94,46.22 36.76,46.22 31.2,51.79 20.15,51.79 17.94,54 v17.33,54
A14  (via drill 0.4)
  Top 0.152: IC1.41 15.29,53.23 v16.72,53.23 | v43.31,71.6 44.03,70.88 IC3.43 44,67.64 44,66.49 v44.38,66.11
  Bottom 0.152: J5.37 41.99,74.9 43.31,73.58 v43.31,71.6 | v16.72,53.23 18.09,53.23 19.84,51.48 31.04,51.48 36.61,45.92 42.25,45.92 42.63,46.3 42.63,50.11 43.92,51.41 43.92,54.99 43.01,55.9 43.01,57.96 42.63,58.26 42.63,65.58 43.16,66.11 v44.38,66.11
A15  (via drill 0.4)
  Top 0.152: IC1.42 | IC1.42 | IC1.42 15.33,52.47 v17.33,52.47 | J5.38 41.94,71.45 43.23,70.16 IC3.44 43.23,66.64 43.69,66.19 v43.69,65.43
  Bottom 0.152: v17.33,52.47 18.24,52.47 19.54,51.18 30.89,51.18 36.45,45.61 42.4,45.61 42.93,46.15 42.93,49.88 44.3,51.25 44.3,55.06 43.31,56.05 43.31,58.11 42.93,58.49 42.93,64.66 v43.69,65.43
AC1
  Top 0.61: F1.1 81.87,30.91 83.7,30.91 J2.1
  Bottom 0.61: JP3.4 75.32,21.23 75.32,28.24 76.61,29.54 83.7,29.54 J2.1
AC2  (via drill 0.4)
  Top 0.61: D3.A 73.87,32.58 73.87,30.07 BR1.4 75.7,28.24 76.08,27.86 v76.15,27.86 | v81.18,22.6 77.83,19.25 JP3.1
  Bottom 0.61: 81.3,22.72 86.36,27.78 89.87,27.78 89.87,29.54 J2.2 90.78,32.28 89.79,33.27 J2.3 | v81.18,22.6 81.3,22.72 | 81.3,22.72 v76.15,27.86
ACF
  Top 0.813: F1.2 77.5,24.1 74.82,24.1 BR1.3 69.25,29.67 69.25,33.62 D3.C
AGND3  (via drill 0.4)
  Top 0.152: IC2.19 48.42,19.78 49.48,19.78 49.71,20.01 C10.2 | 52.3,18.03 52.3,18.56 R8.2 | 52.3,18.03 52.3,17.57 R9.1 52.3,17.11 50.7,17.11 C11.2 49.71,17.34 48.42,17.34 IC2.13 | 52.3,18.03 v51.85,18.03
  Top 0.305: C10.2 50.26,20.54 v51.39,20.54
  pour Ground (no thermals): 66.07,20.29 44.48,20.29 44.48,7.59 66.07,7.59
AGND5  (via drill 0.4)
  Top 0.305: R3.2 8.55,44.63 v8.29,44.9
  Top 0.406: IC1.63 28.45,45.56 28.45,44.39 27.77,43.71 27.77,43.14 | 27.77,43.1 27.77,43.14 | 27.77,43.14 C5.2 27.78,43.11 27.77,43.1 | v25.63,43.78 25.63,43.48 26.17,42.95 27.69,42.95 27.77,43.1
  pour Ground (no thermals): 0.67,68.55 6.38,68.55 12.73,62.2 12.73,52.04 29.24,52.04 29.24,43.78 0.67,43.78
  pour Bottom (isolate 0.305, no thermals): 0.67,68.55 5.43,68.55 12.73,61.25 12.73,52.04 29.24,52.04 29.24,44.1 0.67,44.1
  pour Top (isolate 0.305, no thermals): 0.67,68.55 5.43,68.55 12.73,61.25 12.73,52.04 29.24,52.04 29.24,44.1 0.67,44.1
ALE
  Top 0.152: 15.17,51.63 IC1.43 15.22,51.56 12.98,51.56 12.07,52.47 12.07,61.84 13.52,63.29 13.52,69.84 14.66,70.99 32.19,70.99 32.49,70.68 36,70.68 37.52,69.16 38.59,69.16 39.2,68.55 39.2,66.42 39.65,65.96 41.48,65.96 41.49,65.97 IC3.1
AREF  (via drill 0.4)
  Top 0.152: IC1.62 27.63,44.8 v26.62,43.78
  Supply 0.305: v26.62,43.78 26.62,42.72 25.94,42.03 22.89,42.03 22.59,42.34 10.7,42.34 10.32,42.79 5.44,42.79 3.84,44.39 J6.2
AVCC3  (via drill 0.4)
  Top 0.152: IC2.16 50.17,18.56 50.17,18.83 | 50.17,18.83 50.17,18.87 | 50.17,18.83 C10.1 | 50.25,15.66 50.25,15.59 | 50.25,15.66 C11.1 49.64,15.67 48.73,16.57 IC2.11 | 50.25,15.66 50.25,15.67 | 58.25,12.04 R15.2 58.21,12.01 | 59.92,9.88 59.94,9.86 R20.2 | 62.34,10.71 TR1.15 | 56.72,12.01 C13.1 | LED4.A 56.42,7.51 v56.57,7.67 | LED3.A 66.48,5.15 v65.56,5.15
  Top 0.305: 59.85,10.94 59.92,10.94 | 59.85,10.71 59.85,10.94 | 59.85,10.94 58.21,10.94 58.21,12.01 58.17,12.01 | 59.85,10.71 62.34,10.71 | 59.85,10.71 59.85,9.88 59.92,9.88 | v57.56,13.46 58.17,12.85 58.17,12.01 | 58.17,12.01 56.72,12.01 | 50.25,15.67 v51.39,15.67 | 50.17,18.87 v51.39,18.87
  Top 0.406: FB4.1 55.09,21 v53.83,21
  Bottom 0.152: J1.D2- 95.59,18.41 95.59,13.08 94.52,12.01 J1.D1- 93.91,12.01 89.11,12.01 82.17,5.08 65.64,5.08 v65.56,5.15
  pour Supply (isolate 0.305): 44.48,22.83 66.07,22.83 66.07,1.24 44.48,1.24
  pour Top (isolate 0.305, no thermals): 64.04,5.76 68,5.76 68,1.8 64.04,1.8
  pour Top (isolate 0.305, no thermals): 53.37,5.76 57.33,5.76 57.33,1.8 53.37,1.8
AVCC5  (via drill 0.4)
  Top 0.152: FB2.2
  Top 0.305: J6.3 J6.1 7.65,45.69 8.92,45.69 9.24,45.37 FB2.2 | 29.25,45.57 IC1.64
  Top 0.406: 29.21,43.17 29.4,43.17 C5.1 | 29.25,45.57 29.21,45.54 29.21,43.17 | 29.21,43.17 29.21,42.34 28.83,41.96 26.01,41.96 24.64,43.33 v24.64,43.86
  pour Supply (isolate 0.305, rank 2, no thermals): 5.11,68.55 6.38,68.55 11.46,63.47 11.46,45.05 26.7,45.05 26.7,42.2 5.11,42.2
BE2\
  Top 0.152: R7.2 29.27,12.14 29.7,12.57 IC2.96
CYCLE\
  Top 0.152: IC2.35 45.45,26.38 45.45,28.16 44.75,28.16 RN1.8
D0  (via drill 0.4)
  Top 0.152: IC2.76 | IC2.76 | 52.99,61.23 | 52.99,61.23 IC3.27 51.62,61.17 v50.93,61.16 | 52.99,61.23 53.06,61.23 53.14,61.16 v54.28,61.16 | v20.3,47.67 19.61,46.83 19.23,46.83 18.93,46.53 18.93,45.61 18.87,45.61 IC1.51 | v39.88,37.23 40.04,37.38 41.12,37.38 41.13,37.37 41.23,37.47 41.27,37.44 IC4.13 41.3,37.38 41.33,37.41 41.33,37.46 42.17,37.46 42.4,37.69 42.4,38.38 43.77,39.75 v43.77,39.9 43.77,41.12 45.06,42.41 v45.06,43.63 | IC2.107 37.83,13.15 38.36,13.61 v38.36,15.59 | IC2.76 39.3,20.57 v39.88,21.15
  Bottom 0.152: J5.15 69.86,74.9 68.38,73.43 68.38,71.9 65.71,69.24 59.39,69.24 57.87,67.71 57.87,64.05 54.97,61.16 v54.28,61.16 | v45.06,43.63 46.28,43.63 46.89,43.02 48.8,43.02 50.32,44.55 50.32,55.52 50.63,55.9 50.63,60.85 v50.93,61.16 | v39.88,37.23 40.19,36.93 40.19,32.89 37.37,30.07 37.37,25.19 39.88,22.68 v39.88,21.15 38.36,19.63 v38.36,15.59 | v20.3,47.67 21.52,48.74 29.67,48.74 38.13,40.28 43.39,40.28 v43.77,39.9
D1  (via drill 0.4)
  Top 0.152: IC2.75 | IC2.75 | 41.23,36.16 41.23,36.17 | 41.23,36.16 IC4.14 | 52.99,58.03 52.99,58.02 | 52.99,58.02 IC3.23 | v19.38,47.69 18.82,46.98 18.47,46.98 18.09,46.6 18.09,45.61 18.07,45.61 IC1.50 | IC4.14 | 41.23,36.16 | v39.58,36.16 41.23,36.16 | IC2.106 37.44,11.18 37.44,13.46 37.67,13.69 v37.67,14.75 | v45.98,43.02 45.98,42.72 44.68,41.42 v44.68,40.2 44.68,39.9 42.7,37.92 42.7,36.7 42.17,36.16 IC4.14 | 52.99,58.02 52.98,58.03 52.99,58.03 | 53.06,58.02 53.06,58.03 | 52.99,58.02 53.06,58.02 | v54.28,57.96 53.06,57.96 53.06,58.02 | v51.54,58.19 51.69,58.03 52.99,58.03 | IC2.75 38.33,20.97 v39.2,21.84
  Bottom 0.152: J5.16 69.37,72.36 65.94,68.93 59.54,68.93 58.17,67.56 58.17,63.6 54.28,59.71 v54.28,57.96 | v39.58,36.16 39.88,35.86 39.88,33.19 37.06,30.37 37.06,24.96 39.2,22.83 v39.2,21.84 37.67,20.31 v37.67,14.75 | v19.38,47.69 20.88,49.04 29.82,49.04 38.28,40.59 44.3,40.59 v44.68,40.2 | v51.54,58.19 50.93,57.73 50.93,55.75 50.63,55.37 50.63,44.24 49.1,42.72 46.28,42.72 v45.98,43.02
D2  (via drill 0.4)
  Top 0.152: IC2.74 | IC2.74 | 52.91,62.76 IC3.29 52.91,62.76 | 52.91,62.76 v54.28,62.76 | v18.51,47.69 18.51,47.55 17.94,46.98 17.25,46.98 17.25,45.57 IC1.49 | v39.27,34.79 41.2,34.79 IC4.15 41.3,34.95 41.33,34.97 41.33,34.95 42.25,34.95 43.01,35.71 43.01,37.61 45.6,40.2 v45.6,40.51 45.6,41.65 46.97,43.02 v46.97,43.78 | IC2.105 37.06,11.2 37.06,13.92 v36.99,13.99 | 52.91,62.76 50.4,62.76 v50.09,63.06 | IC2.74 38.04,21.37 38.44,21.76 v38.44,22.52
  Bottom 0.152: v39.27,34.79 39.58,34.49 39.58,33.5 36.76,30.68 36.76,24.81 38.21,23.29 38.44,23.06 v38.44,22.52 38.44,21.76 36.99,20.31 | v18.51,47.69 20.24,49.35 29.98,49.35 38.44,40.89 45.22,40.89 v45.6,40.51 | v50.09,63.06 50.32,62.84 50.32,56.05 50.02,55.67 50.02,44.78 49.03,43.78 v46.97,43.78 | v36.99,13.99 36.99,20.31 | 36.99,20.31 36.99,20.33 | J5.17 66.02,73.58 66.02,72.05 63.81,69.84 59.09,69.84 57.26,68.02 57.26,64.89 55.12,62.76 v54.28,62.76
D3  (via drill 0.4)
  Top 0.152: IC2.73 | IC2.73 | 52.73,33.57 IC4.17 52.68,33.57 v49.48,33.65 v45.45,33.65 | IC3.28 52.96,62 52.91,62 52.99,61.92 | 52.99,61.92 v54.74,61.92 | v51.54,61.92 52.99,61.92 | IC1.48 15.27,47.61 15.27,47.67 v16.79,47.67 | IC2.104 36.61,11.2 36.61,13.08 v36.45,13.23 | IC2.73 37.38,21.77 v37.6,21.99
  Bottom 0.152: J5.18 67.31,72.36 64.5,69.54 59.24,69.54 57.56,67.86 57.56,64.51 54.97,61.92 v54.74,61.92 | v16.79,47.67 17.63,47.67 19.61,49.65 30.13,49.65 38.59,41.19 45.9,41.19 46.36,40.74 46.36,34.56 v45.45,33.65 44.53,33.65 40.26,37.92 39.65,37.92 38.59,36.85 38.59,33.04 36.45,30.91 36.45,24.66 37.75,23.29 37.75,22.14 v37.6,21.99 36.61,21 36.61,15.13 36.3,14.83 36.3,13.38 v36.45,13.23 | v51.54,61.92 51.85,61.92 52.46,61.31 52.46,55.9 51.24,54.68 51.24,41.8 48.95,39.52 48.95,34.18 v49.48,33.65
D4  (via drill 0.4)
  Top 0.152: IC2.71 | IC2.71 | IC4.18 52.73,34.97 51.34,34.97 v49.71,34.95 v47.12,34.95 v45.45,34.95 | 52.92,64.36 IC3.31 | 52.92,64.36 52.91,64.36 | 52.99,64.28 52.92,64.35 52.92,64.36 | v54.28,64.36 53.06,64.36 52.99,64.28 | 52.99,64.28 52.99,64.36 v50.4,64.36 | IC1.47 15.37,48.51 15.45,48.43 v17.4,48.43 | IC2.102 35.84,11.18 35.84,13.92 36.07,14.14 36.07,15.44 v36,15.52 | IC2.71 36.88,22.57 v37.14,22.83
  Bottom 0.152: v54.28,64.36 54.97,64.36 56.65,66.03 56.65,68.32 58.78,70.45 61.9,70.45 63.51,72.05 63.51,72.97 64.8,74.27 J5.19 | v17.4,48.43 17.79,48.43 19.31,49.96 30.28,49.96 38.74,41.5 46.13,41.5 46.66,40.97 46.66,35.4 v47.12,34.95 | v45.45,34.95 43.77,34.95 40.49,38.22 39.43,38.22 38.28,37.08 38.28,33.19 36.15,31.06 36.15,24.43 37.14,23.44 v37.14,22.83 36,21.69 v36,15.52 | v49.71,34.95 49.26,35.4 49.26,39.29 51.54,41.57 51.54,54.53 52.76,55.75 52.76,62.15 52,62.91 51.24,62.91 50.4,63.75 v50.4,64.36
D5  (via drill 0.4)
  Top 0.152: IC2.70 | IC2.70 | IC2.70 36.03,22.97 v36.23,23.17 | IC4.19 51.32,36.17 | 52.91,63.52 52.91,63.55 IC3.30 52.93,63.54 52.91,63.52 | 52.91,63.52 v54.74,63.52 | v51.54,63.52 52.91,63.52 | v50.09,36.16 51.32,36.17 | v50.09,36.16 51.31,36.17 51.32,36.17 | v50.09,36.16 v47.35,36.16 v45.45,36.16 | IC1.46 15.26,49.2 v16.79,49.2 | v35.46,14.75 35.54,14.68 35.54,12.85 35.39,12.7 35.39,11.21 IC2.101
  Bottom 0.152: v54.74,63.52 56.95,65.73 56.95,68.17 58.93,70.15 62.59,70.15 J5.20 | v16.79,49.2 17.56,49.2 18.62,50.26 30.43,50.26 38.89,41.8 46.36,41.8 46.97,41.19 46.97,36.55 v47.35,36.16 | v35.46,14.75 35.23,14.98 35.23,22.47 35.73,22.97 36.03,22.97 v36.23,23.17 36.23,23.82 35.84,24.2 35.84,31.21 37.98,33.35 37.98,37.38 39.12,38.53 40.72,38.53 43.08,36.16 v45.45,36.16 | v51.54,63.52 52.61,63.52 53.06,63.06 53.06,55.6 51.85,54.38 51.85,41.35 49.56,39.06 49.56,36.7 v50.09,36.16
D6  (via drill 0.4)
  Top 0.152: IC2.69 | IC2.69 | v35.43,23.57 35.23,23.37 IC2.69 | 15.33,49.97 | 15.33,49.97 IC1.45 | IC4.20 52.73,37.47 51.32,37.47 v50.4,37.46 v47.66,37.46 v45.45,37.46 | IC3.33 52.91,65.96 | IC3.33 | IC3.33 v54.28,65.96 | v51.16,65.96 IC3.33 | 15.33,49.97 15.34,49.96 v17.4,49.96 | IC2.100 35.01,11.2 | v34.93,13.99 35.08,13.84 35.08,12.85 35.01,12.77 35.01,11.2 | 35.01,11.2 35.01,11.17
  Bottom 0.152: v51.16,65.96 51.01,65.73 51.01,64.82 51.54,64.28 52.38,64.28 53.37,63.29 53.37,55.44 52.15,54.22 52.15,41.04 49.87,38.76 49.87,37.99 v50.4,37.46 | v54.28,65.96 55.35,65.96 56.04,66.64 56.04,68.63 58.48,71.06 60.3,71.06 60.99,71.75 60.99,73.63 J5.21 | v17.4,49.96 18.01,50.57 30.59,50.57 39.04,42.11 46.59,42.11 47.27,41.42 47.27,37.84 v47.66,37.46 | v34.93,13.99 34.78,14.14 34.78,15.52 34.93,15.67 34.93,23.07 v35.43,23.57 35.45,23.59 35.46,23.59 35.54,23.67 35.54,31.36 37.67,33.5 37.67,37.61 38.89,38.83 41.03,38.83 42.4,37.46 v45.45,37.46
D7  (via drill 0.4)
  Top 0.152: IC2.68 | IC2.68 | IC1.44 | IC1.44 | 52.7,38.67 IC4.21 52.71,38.68 v50.86,38.68 v47.96,38.68 v45.45,38.68 | v54.74,65.2 52.96,65.2 IC3.32 52.88,65.12 v51.62,65.12 | 15.27,50.8 15.25,50.77 IC1.44 | 15.27,50.8 15.29,50.78 | 15.27,50.8 15.35,50.87 v16.79,50.87 | v34.47,13.23 34.62,13.23 IC2.99 | v34.62,24.05 33.86,24.05 33.56,23.74 32.49,23.74 32.47,23.77 IC2.68
  Bottom 0.152: J5.22 62.29,72.36 60.69,70.76 58.63,70.76 56.34,68.47 56.34,66.34 55.2,65.2 v54.74,65.2 | v16.79,50.87 30.74,50.87 39.2,42.41 46.82,42.41 47.96,41.27 v47.96,38.68 | v34.47,13.23 34.32,13.38 34.32,15.59 34.62,15.9 v34.62,24.05 34.62,30.91 37.37,33.65 37.37,37.92 38.59,39.14 41.25,39.14 41.71,38.68 v45.45,38.68 | v51.62,65.12 52.84,65.12 53.68,64.28 53.68,55.29 52.46,54.07 52.46,40.74 50.86,39.14 v50.86,38.68
DC  (via drill 0.4)
  Top 0.61: 66.23,39.98 66.07,39.82 C33.1 66.55,39.67 67.39,39.67 | BR1.1 64.04,28.24 59.24,28.24 C19.+ | 67.39,39.67 67.92,39.67 IC8.3 | v67.39,39.98 67.39,39.67 | v66.32,30.45 65.94,30.07 BR1.1 | JP6.1 13.25,10.5 13.21,10.45 13.97,9.69 D2.C 14,7.59 | BR1.1 64.04,28.19 64.17,27.91
  Top 0.813: v14,1.56 14,7.59 | v64.17,26.64 64.17,27.91 63.85,28.23
  Bottom 0.61: J5.10 77.6,71.67 77.6,65.35 72.27,60.02 72.27,44.85 v67.39,39.98 67.16,39.75 67.16,31.29 v66.32,30.45
  Bottom 0.813: v14,1.56 53.6,1.56 53.6,1.57 60.08,1.57 60.08,6.68 64.19,6.68 64.19,7.97 v64.17,26.64
DCX
  Top 0.61: J4.4 | J4.4 10.81,10.13 JP6.2 11.25,10.5 11.3,10.45 9.9,9.05 D2.A
DE485
  Top 0.152: IC7.3 25.75,15.85 24.95,16.64 24.95,19.02 R27.2 24.95,19.65 25.07,19.77 JP2.2 | JP2.2 JP2.4 | JP2.2 25.07,23.35
DIHO  (via drill 0.4)
  Top 0.152: IC7.4 26.93,17.11 27.01,17.19 v27.01,18.03 | v70.06,63.6 74.71,63.6 76,64.89 IC6.11 | v68.84,62.38 66.55,60.09 62.44,60.09 61.83,59.48 JP1.4
  Bottom 0.152: 29.67,11.71 26.78,11.71 26.24,12.24 26.24,13.23 27.01,13.99 v27.01,18.03 | JP1.4 60.55,58.49 58.4,58.49 53.06,53.16 53.06,39.14 51.54,37.61 51.54,30.98 44.99,24.43 44.99,13.23 43.46,11.71 29.67,11.71 | v68.84,62.38 v70.06,63.6 | 29.67,11.71 29.75,11.71
ENEEP
  Top 0.152: R14.2 49.71,14.37 49.56,14.52 48.42,14.52 IC2.6
GND  (via drill 0.4)
  Top 0.152: 66.07,45.21 C34.2 65.94,45.24 | 69.66,45.21 IC8.1 69.88,45.12 | 63.53,35.53 IC9.2 63.48,35.53 | IC9.4 57.18,35.53 | C36.- 58.61,42.52 | v30.59,32.05 30.66,32.05 31.04,32.43 IC5.7 | v42.63,33.57 42.02,33.57 IC4.16 | IC1.53 | IC1.53 | IC3.17 | IC3.17 | v22.26,19.65 R27.1 | C31.1 77.53,51.88 v78.77,51.88 | 59.77,39.29 59.79,39 | C3.2 25.84,64.11 25.79,64.05 25.73,64.11 C2.2 | C1.2 16.03,64.13 15.96,64.05 v14.74,64.05 | 32.41,13.79 IC2.93 32.43,13.84 | 32.41,17.75 32.41,17.34 31.65,17.34 | 32.41,17.75 IC2.83 | IC2.82 32.41,18.15 32.41,17.75 | 32.43,16.2 IC2.87 32.43,15.82 | IC2.88 32.43,15.82 | 32.43,15.82 32.41,15.82 | IC2.89 IC2.88 | IC2.89 32.41,15.36 | IC2.90 32.43,14.6 | IC2.90 IC2.89 | IC2.90 32.41,14.98 | 32.43,14.6 IC2.91 32.43,14.22 | 32.43,14.6 32.41,14.6 | 32.43,14.22 IC2.92 32.43,13.84 | 32.43,14.22 32.41,14.22 | 32.43,13.84 32.41,13.84 | IC2.72 32.41,22.14 30.27,22.14 C9.2 | IC2.103 36.23,9.31 C15.2 | IC2.57 36.61,26.39 36.61,28.04 C6.2 | C16.2 40.49,9.18 40.49,9.95 41.56,9.95 41.83,10.23 IC2.117 41.79,11.17 41.79,12.47 38.21,12.47 38.21,11.17 IC2.108 | C17.2 43.62,9.18 v43.62,8.05 | IC2.24 47.66,21.77 47.66,21.76 v49.26,21.76 | R8.1 52.71,20.82 v52.71,21.46 | IC2.67 32.39,24.12 30.21,24.12 v30.21,23.13 | IC2.39 43.84,26.37 v43.84,24.96 | IC2.52 38.66,26.37 38.66,28.16 v38.05,28.16 | C7.2 39.4,31.03 v40.34,31.97 40.95,31.06 R5.1 | R6.1 47.66,32.13 v46.05,32.13 46.07,32.13 C8.2 | 51.69,9.18 51.69,9.19 | 51.69,9.18 C18.2 | 51.69,9.11 51.69,9.18 | 31.65,17.34 29.6,17.34 v29.6,16.73 30.59,15.74 32.41,15.74 32.41,15.75 IC2.88 | 31.65,17.34 IC2.84 | 27.85,3.4 S1.3 | S1.4 17.86,3.41 17.86,3.4 22.8,3.4 v22.87,3.46 22.93,3.4 27.85,3.4
  Top 0.152: 27.85,3.4 28,3.4
  Top 0.305: IC3.25 52.94,59.56 54.59,59.56 54.99,59.15 C41.2 55.65,59.1 v56.88,59.1 | 25.25,61.59 IC1.22 | C3.2 25.25,63.16 25.25,61.59 | v25.25,60.09 25.25,61.59 | 70.07,67.95 C22.2 | 70.07,67.95 70.06,67.94 70.07,67.93 C23.2 69.91,67.75 69.91,65.72 IC6.16 | 70.07,67.95 70.08,67.94 v71.35,67.94 | R23.1 19.26,18.41 21.29,18.41 | 21.29,18.41 21.29,18.4 v21.3,18.38 | IC7.5 21.29,17.13 21.29,18.41 | R3.1 v9.55,41.88 | IC3.17 47.24,56.28 47.27,56.28 47.27,54.17 | C39.2 47.27,54.17 | 47.27,54.17 v47.35,53.31 | C37.2 36.02,40.38 v36,40.36 | 36.61,28.04 36.73,28.16 v38.05,28.16 | C15.2 36.3,9.18 v36.3,8.05 | C16.2 40.42,9.18 v40.42,8.05 | 30.27,22.14 30.21,22.21 v30.21,23.13 | IC3.4 41.48,63.52 v39.96,63.52
  Top 0.406: C32.2 24.98,9.37 v24.95,9.34 | 66.07,45.21 66.09,45.23 | 69.66,45.21 69.64,45.23 66.09,45.23 | 66.09,45.23 v66.09,46.53 | C33.2 66.06,41.42 v64.72,41.42 | 57.33,39.34 57.33,39.44 58.55,39.44 C36.- | C20.- 58.55,48.2 v56.57,48.2 | C40.2 52.29,69.77 v53.6,69.77 | v56.08,51.25 56.11,51.25 | v56.08,51.25 v56.07,51.25 | C38.2 54.68,51.25 v56.08,51.25 | IC1.53 20.43,43.69 C4.2 20.22,42.87 21.74,41.35 | 21.74,41.35 21.75,41.35 | 21.74,41.35 JP4.10A | v53.22,6.68 53.22,9.11 51.69,9.11 | R14.1 51.78,13.94 51.78,12.35 | C18.2 51.78,9.18 51.78,12.35 | 51.78,12.35 C12.2 | C14.2 v31.14,7.59 | LED1.C H4.B3,0 | 63.51,35.53 63.48,35.53 | IC9.4 63.51,35.53 | 63.51,35.53 IC9.2 | C35.2 66.09,35.95 66.09,35.78 63.78,35.78 63.53,35.53
  Top 0.61: R26.2 v20.98,10.77 | BR1.2 64.97,24.12 v62.97,24.12 58.47,24.12 C19.-
  Bottom 0.61: R32.1 J3.5
  other vias: 55.91,38.7 57.18,38.7 58.45,38.7 59.72,38.7 55.91,32.35 57.18,32.35 58.45,32.35 59.72,32.35 19.84,57.88 26.85,57.88 36.83,57.12 39.43,13.46 41.33,22.98 42.93,21.69 42.02,15.13
  pour Ground (no thermals): 0.67,77.44 97.19,77.44 97.19,24.1 66.07,24.1 66.07,21.56 43.21,21.56 43.21,6.32 97.19,6.32 97.19,1.24 0.67,1.24 0.67,42.52 30.51,42.52 30.51,53.31 14,53.31 14,63.47 7.65,69.82 0.67,69.82
  pour Top (isolate 0.203, rank 3, no thermals): 60.99,31.72 55.27,31.72 55.27,39.34 60.99,39.34
  pour Top (isolate 0.305, no thermals): 79.89,5.76 83.85,5.76 83.85,1.8 79.89,1.8
  pour Bottom (isolate 0.305): 0.67,77.44 97.19,77.44 97.19,70.77 90.52,70.77 90.52,44.42 97.19,44.42 97.19,24.1 66.07,24.1 66.07,21.56 43.21,21.56 43.21,6.32 97.19,6.32 97.19,1.24 0.67,1.24 0.67,42.83 30.51,42.83 30.51,53.31 14,53.31 14,63.79 7.97,69.82 0.35,69.82 0.67,70.14
  pour Top (isolate 0.305): 0.67,77.44 97.19,77.44 97.19,50.77 71.15,50.77 71.15,34.26 97.19,34.26 97.19,24.1 66.07,24.1 66.07,21.56 43.21,21.56 43.21,6.32 52.1,6.32 52.1,1.24 0.67,1.24 0.67,42.83 30.51,42.83 30.51,53.31 14,53.31 14,63.79 7.97,69.82 0.67,69.82
  pour Top (isolate 0.305): 85.75,6.32 97.19,6.32 97.19,0.6 85.75,0.6
GNDN  (via drill 0.4)
  other vias: 67.7,22.53 67.7,7.89
  pour Ground (isolate 0.305): 67.34,22.83 97.19,22.83 97.19,7.59 67.34,7.59
  pour Bottom (isolate 0.305, no thermals): 67.34,22.83 97.19,22.83 97.19,7.59 67.34,7.59 67.34,22.51
  pour Top (isolate 0.305, no thermals): 67.34,22.83 97.19,22.83 97.19,7.59 67.34,7.59
HI
  Top 0.152: IC6.10 77.22,64.89 75.32,62.99 63.81,62.99 JP1.7
LCLK
  Top 0.152: IC2.42 42.63,27.55 42.17,27.55 41.03,28.7 41.03,29.24 R5.2
LEDA\  (via drill 0.4)
  Top 0.152: v61.75,4.47 60,4.47 LED4.C 59.16,3.83 59.16,5.76 57.64,7.29 57.64,8.94 R17.2
  Bottom 0.152: v61.75,4.47 89.41,4.47 93.15,8.2 93.15,8.43 95.2,8.43 J1.D1+
  pour Top (isolate 0.305, no thermals): 58.25,5.76 62.21,5.76 62.21,1.8 58.25,1.8
LEDB\  (via drill 0.4)
  Top 0.152: v81.87,6.22 74.86,6.22 74.86,4.39 70.74,4.39 LED3.C 69.22,2.49 69.22,1.34 63.28,1.34 63.28,3.57 R18.2
  Bottom 0.152: v81.87,6.22 87.81,12.31 93.3,17.8 93.3,20.31 93.91,20.92 J1.D2+
  pour Top (isolate 0.305, no thermals): 69.22,5.76 73.18,5.76 73.18,1.8 69.22,1.8
N$1
  Top 0.152: IC6.3 69.88,54.96 69.45,54.53 68.31,54.53 68,54.22 68,53.54 67.97,53.51 C28.2
N$4
  Top 0.152: R6.2 47.2,29 47.2,25.34 46.51,25.34 46.44,25.27 44.84,25.27 44.68,25.42 44.68,25.57 IC2.37
N$5
  Top 0.152: TR1.1 76.29,9.5 77.56,10.77 J1.1
N$6
  Top 0.152: C2.1 22.39,63.79 22.43,63.75 22.43,63.37 22.74,63.06 24.19,63.06 24.43,62.81 IC1.23 | Y1.P$2 24.81,66.03 22.89,66.03 22.43,65.58 22.43,64.28 22.36,64.21 22.38,64.18 C2.1 | C2.1 22.36,64.13 20.91,64.13 R1.2
N$7
  Top 0.152: IC1.19 27.63,62.32 28.38,63.06 29.98,63.06 30.89,63.98 37.37,63.98 38.13,63.22 Y2.2
N$10
  Top 0.152: IC1.24 23.63,62.62 23.5,62.76 19.61,62.76 19.23,63.14 19.23,64.05 R1.1 19.21,64.11 19.23,64.13 17.71,64.13 | C1.1 17.71,64.13 | Y1.P$1 17.71,66.76 17.71,64.13
N$12
  Top 0.152: TR1.3 J1.2
N$15
  Top 0.152: C31.2 76.2,53.5 74.96,54.74 IC6.7
N$16
  Top 0.152: R19.2 32.8,6.14 33.41,6.75 33.41,10.41 33.79,10.41 IC2.97
N$20  (via drill 0.4)
  Top 0.152: R25.1 16.07,13.62 v14.84,13.62
  Bottom 0.152: JP6.9 13.43,18.57 14.66,17.34 14.66,13.81 v14.84,13.62
N$21
  Top 0.152: JP4.1B 19.16,23.59 18.7,23.59 17.79,24.51 13.59,24.51 J7.1
N$22
  Top 0.152: TR1.6 72.42,15.85 72.74,15.53 72.74,15.21 73.37,14.58 76.23,14.58 77.5,15.85 82.58,15.85 84.48,13.94 J1.3
N$23
  Top 0.152: IC1.18 28.43,62.51 28.68,62.76 30.21,62.76 31.12,63.67 33.79,63.67 35.54,61.92 35.54,58.49 35.62,58.41 Y2.1
N$24
  Top 0.152: J1.6 81.56,17.5 74.4,17.5 73.56,18.33 71.05,18.33 71.05,18.36 TR1.8
N$25
  Top 0.152: R9.2 52.3,15.9 51.69,16.5 49.26,16.5 48.8,16.96 48.42,16.96 IC2.12
N$26
  Top 0.152: R21.2 73.21,17.11 TR1.7
N$27
  Top 0.152: R10.2 60.23,18.03 61.45,18.03 TR1.9
N$31
  Top 0.152: C29.1 71.15,51.79 70.13,51.79 70.13,54.38 70.52,54.76 70.52,57.42 70.21,57.73 68.84,57.73 68.61,57.5 IC6.2
N$32
  Top 0.152: R22.2 69.71,8.07 68.93,8.86 68.93,10.13 69.56,10.77 TR1.2 71.15,10.77
N$33
  Top 0.152: R11.2 60.23,15.52 61.45,15.52 TR1.11
N$38
  Bottom 0.152: JP4.2B 18.71,24.35 16.49,24.35 16.18,24.05 11.51,24.05 J7.2
N$43
  Top 0.152: R28.1 74.48,3.32 77.22,3.32 LED1.A
  pour Top (isolate 0.305, no thermals): 78.67,5.76 75.01,5.76 75.01,1.8 78.97,1.8 78.97,5.76
N$44  (via drill 0.4)
  Top 0.152: C21.1 76.55,12.99 74.33,12.99 R21.1 | R22.1 74.33,10.77 | R22.1 74.17,10.92 | R22.1 74.35,10.94 v76.23,10.94
  Bottom 0.152: v76.23,10.94 78.14,12.85 C21.1
N$45
  Top 0.152: JP4.4B 19.12,29.36 18.23,28.47 13.83,28.47 13.33,28.97 11.23,28.97 10.19,27.93 J7.4
N$48
  Top 0.152: JP4.5B 19.21,31.36 18.33,30.47 12.73,30.47 J7.5
N$49
  Top 0.152: JP4.6B 19.12,33.35 18.23,32.47 13.93,32.47 13.33,31.87 11.63,31.87 10.21,30.45 J7.6
N$50
  Top 0.152: JP4.7B 19.12,35.35 18.23,34.47 14.23,34.47 12.73,32.97 J7.7
N$51
  Top 0.152: J7.8 10.19,33.03 11.63,34.47 13.53,34.47 15.53,36.47 15.57,36.47 | JP4.8B 19.2,37.35 18.32,36.47 15.57,36.47 | 15.57,36.47
N$52
  Top 0.152: JP4.9B 19.21,39.35 18.33,38.47 16.83,38.47 13.93,35.57 12.73,35.57 J7.9
N$56
  Top 0.152: C29.2 IC6.4
N$57
  Top 0.152: C30.2 74.33,54.26 73.69,54.9 IC6.6
N$58
  Top 0.152: C30.1 73.09,51.85 72.42,52.52 IC6.5
N$59
  Top 0.152: J4.3 | 11.14,12.67 11.16,12.67 JP6.4 11.24,12.58 11.14,12.67 | J4.3 11.14,12.67 | R26.1 15.59,11.56 12.25,11.56 11.14,12.67
N$60  (via drill 0.4)
  Top 0.152: C24.1 81.83,64.17 82.63,64.17 82.63,62.37 82.83,62.17 83.03,62.17 RN2.3 83.48,61.88 83.85,61.88 84.17,61.56 85.12,61.56 v85.44,61.25
  Bottom 0.152: J3.7 90.2,55.85 88.93,57.12 88.93,59.66 88.61,59.98 86.07,59.98 85.44,60.61 v85.44,61.25
N$61  (via drill 0.4)
  Top 0.152: RN2.1 83.43,60.17 83.43,58.97 C27.1 84.23,58.37 v85.03,58.37
  Bottom 0.152: v85.03,58.37 85.03,57.77 87.63,57.77 88.83,56.57 88.83,53.57 89.83,52.57 J3.8
N$62  (via drill 0.4)
  Top 0.152: C25.1 83.43,64.17 83.43,62.97 RN2.4 83.83,62.57 84.23,62.57 v84.43,62.37
  Bottom 0.152: v84.43,62.37 84.43,56.37 87.03,56.37 J3.2
N$63
  Top 0.152: RN2.2 83.03,60.97 82.83,60.77 82.63,60.77 82.63,58.97 81.83,58.97 C26.1 81.83,58.17 82.23,57.77 84.63,57.77 85.23,57.17 86.43,57.17 86.43,55.57 87.03,54.97 87.43,54.97 87.43,53.97 J3.3
N$65
  Top 0.152: RN2.5 81.34,62.99 79.05,65.27 79.05,67.18 72.11,67.18 71.43,66.49 IC6.15
N$66
  Top 0.152: RN2.8 81.43,60.17 78.03,56.77 78.03,54.97 76.83,54.97 76.43,55.37 IC6.8
N$67  (via drill 0.4)
  Top 0.152: v78.44,62.68 78.44,66.8 72.95,66.8 72.65,66.49 IC6.14 | v80.8,61.16 RN2.7
  Bottom 0.152: v80.8,61.16 78.97,61.92 v78.44,62.68
N$68
  Top 0.152: R23.2 15.27,18.38 13.52,16.64 13.32,16.64 JP6.7
N$69
  Top 0.152: RN2.6 81.43,61.77 80.23,61.77 77.63,59.17 77.63,56.97 IC6.9
N$70
  Top 0.152: R24.2 15.27,15.85 14,14.58 JP6.5 | JP6.5
N$73
  Bottom 0.152: JP4.10B 19.71,40.99 19.08,40.36 14.96,40.36 10.16,35.55 J7.10
NICRST  (via drill 0.4)
  Top 0.152: R31.2 57.03,66.8 57.03,65.2 R30.2 57.03,64.28 57.03,62.68 R29.2 57.56,61.77 58.09,61.23 59.31,61.23 v59.31,57.65 | v50.09,24.2 48.42,24.2 IC2.30
  Bottom 0.152: v59.31,57.65 58.09,57.65 53.37,52.93 53.37,38.91 51.85,37.38 51.85,25.95 v50.09,24.2
NICSEL\  (via drill 0.4)
  Top 0.152: 43.01,26.39 IC2.41 43.01,26.37 43.01,27.93 v43.23,28.16 43.12,28.28 RN1.6 | IC3.2 42.35,65.17 43.08,64.44 47.88,64.44 50.32,61.92 50.32,60.78 50.55,60.55 51.24,60.55 v51.54,60.24
  Bottom 0.152: v51.54,60.24 52.15,59.63 52.15,56.05 50.93,54.83 50.93,42.03 48.65,39.75 48.65,30.45 46.36,28.16 v43.23,28.16
NICWR\
  Top 0.152: IC2.36 44.99,26.41 44.99,27.71 43.92,27.71 43.92,29 RN1.7
NLEDA\  (via drill 0.4)
  Top 0.152: R17.1 55,9.88 v54.13,9.88 | IC2.22 48.75,20.97 v49.03,20.7
  Bottom 0.152: v54.13,9.88 61.3,9.88 62.06,10.64 62.06,15.21 55.12,22.14 51.16,22.14 49.71,20.7 v49.03,20.7
NLEDB\  (via drill 0.4)
  Top 0.152: v62.74,8.2 62.74,5.53 R18.1 | v46.21,21.76 46.66,21.38 46.89,21.38 IC2.23
  Bottom 0.152: v46.21,21.76 46.97,22.52 55.73,22.52 62.74,15.52 v62.74,8.2
NXTAL1
  Top 0.152: IC2.127 45.83,10.26 45.37,9.8 45.37,9.19 | R16.2 46.82,9.19 45.37,9.19 | Y3.P$2 39.09,5.02 39.12,5 41.25,7.13 43.92,7.13 45.3,8.52 C17.1 45.37,9.11 45.37,9.19
NXTAL2
  Top 0.152: IC2.128 46.28,11.12 46.28,10.33 46.36,10.26 47.58,10.26 48.49,9.34 48.49,9.19 R16.1 | Y3.P$1 48.57,5.08 48.57,9.11 R16.1 | R16.1 48.56,9.18 48.57,9.19 48.58,9.18 C18.1
PB0  (via drill 0.4)
  Top 0.152: IC1.10 31.17,54.83 v29.75,54.83
  Bottom 0.152: v29.75,54.83 31.58,54.83 31.96,55.21 31.96,70.53 30.59,71.9 30.59,73.55 J5.47
PB1  (via drill 0.4)
  Top 0.152: IC1.11 | IC1.11 | IC1.11 31.21,55.6 v29.29,55.6 28.99,55.29 28.99,54.53 29.44,54.07 29.44,47.06 29.9,46.6 29.9,45 30.21,45 30.21,42.49 28.07,40.36 21.06,40.36 20.76,40.05 20.76,36.93 20.22,36.39 18.78,36.39 17.71,35.33 | 17.71,35.33 | JP4.7C 17.71,35.33
  Bottom 0.152: v29.29,55.6 31.65,55.6 31.65,69.95 J5.48
PB2  (via drill 0.4)
  Top 0.152: 31.23,56.47 IC1.12 | 31.23,56.47 31.13,56.37 | 31.23,56.47 31.12,56.36 v29.75,56.36
  Bottom 0.152: v29.75,56.36 31.35,56.36 31.35,69.39 29.37,71.37 28.61,71.37 27.92,72.05 27.92,73.27 26.7,74.49 J5.49
PB3  (via drill 0.4)
  Top 0.152: 31.43,57.17 31.33,57.17 IC1.13 31.14,57.27 v29.29,57.27
  Bottom 0.152: J5.50 26.78,72.36 28.07,71.06 29.06,71.06 31.04,69.08 31.04,57.27 v29.29,57.27
PB4  (via drill 0.4)
  Top 0.152: 31.33,57.97 IC1.14 31.17,58.03 v29.75,58.03
  Bottom 0.152: J5.51 25.71,73.35 25.71,71.83 26.78,70.76 28.76,70.76 30.74,68.78 30.74,58.03 v29.75,58.03
PB5  (via drill 0.4)
  Top 0.152: IC1.15 31.13,58.87 31.06,58.8 | 31.06,58.8 31.03,58.77 | v29.29,58.8 31.06,58.8
  Bottom 0.152: J5.52 24.19,72.36 26.09,70.45 28.45,70.45 30.43,68.47 30.43,58.8 v29.29,58.8
PB6  (via drill 0.4)
  Top 0.152: 31.23,59.67 IC1.16 | 31.23,59.67 31.13,59.57 | 31.23,59.67 31.12,59.56 v29.75,59.56
  Bottom 0.152: 21.62,74.92 21.6,74.95 | 21.62,74.92 J5.53 | 21.62,74.92 23.12,73.43 23.12,71.45 24.41,70.15 28.15,70.15 30.13,68.17 30.13,60.4 v29.75,59.56
PB7  (via drill 0.4)
  Top 0.152: v28.15,59.86 28.45,59.86 29.21,60.62 29.21,61.54 29.23,61.56 IC1.17
  Bottom 0.152: J5.54 21.62,72.33 24.11,69.84 27.84,69.84 29.82,67.86 29.82,61.84 28.15,60.17 v28.15,59.86
PD0  (via drill 0.4)
  Top 0.152: IC1.25 v22.83,59.57 | IC1.25
  Bottom 0.152: J5.55 19.08,74.88 19.16,74.8 19.16,73.66 19.46,73.35 19.61,73.35 20.07,72.89 20.07,71.83 19.61,71.37 18.7,71.37 17.48,70.15 15.04,70.15 13.82,68.93 13.82,63.06 14.05,62.84 20.15,62.84 22.81,60.17 22.81,59.56 v22.83,59.57
PD1  (via drill 0.4)
  Top 0.152: IC1.26 22.03,61.67 v22.03,59.97
  Bottom 0.152: J5.56 17.18,70.45 14.74,70.45 13.52,69.24 13.52,62.68 13.67,62.53 19.46,62.53 22.05,59.94 22.05,59.86 v22.03,59.97
PD2  (via drill 0.4)
  Top 0.152: IC1.27 v21.23,59.57 | IC1.27 | JP1.9 63.27,65.2 63.28,65.2 65.26,66.87 65.56,67.18 65.56,70.91 66.25,71.6 66.25,76.25 65.41,77.08 35.92,77.08 35.39,76.55 17.4,76.55 16.54,75.69 J5.57
  Bottom 0.152: v21.23,59.57 21.23,59.62 21.21,59.63 21.21,60.17 19.16,62.23 13.52,62.23 13.21,62.53 13.21,69.54 14.43,70.76 16.72,70.76 17.71,71.75 17.71,73.73 J5.57
PD3  (via drill 0.4)
  Top 0.152: IC1.28 v20.43,59.97 | IC1.28 | J5.58 17.86,73.68 17.86,75.79 18.24,76.17 35.69,76.17 36.23,76.7 64.95,76.7 65.87,75.79 65.87,71.9 64.8,70.84 v64.8,68.25
  Bottom 0.152: v20.43,59.97 20.45,59.94 20.45,60.02 18.55,61.92 13.37,61.92 12.91,62.38 12.91,69.84 14.13,71.06 15.24,71.06 J5.58 | JP1.3 64.06,59.2 64.8,59.94 v64.8,68.25
PD4  (via drill 0.4)
  Top 0.152: IC1.29 | IC1.29 | IC1.29 v19.63,59.57 20.33,58.87 27.23,58.87 28,58.11 v28,48.05 | v28.83,29.08 28.61,28.85 26.47,28.85 25.02,27.4 25.06,27.37 JP2.6
  Bottom 0.152: J5.59 14.02,74.9 14.05,74.88 14.05,73.5 14.2,73.35 14.58,73.35 15.04,72.89 15.04,71.83 14.58,71.37 13.82,71.37 12.6,70.15 12.6,62.23 13.21,61.62 18.24,61.62 19.61,60.24 19.61,59.56 v19.62,59.57 v19.63,59.57 | v28.83,29.08 28.38,29.54 28.38,35.02 28,35.4 v28,48.05
PD5  (via drill 0.4)
  Top 0.152: IC1.30 18.85,61.55 v18.85,60.02 18.85,49.8 19.84,48.81 21.44,48.81 v22.13,48.13 | IC1.30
